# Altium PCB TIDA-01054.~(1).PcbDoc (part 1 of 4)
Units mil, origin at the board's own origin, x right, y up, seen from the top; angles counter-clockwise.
Board outline 4448 x 3930 mil, 4 copper layers (Layer 1 - Top Layer, Layer 2 - GND, Layer 3 - PWR, Layer 4 - Bottom Layer), stack 59.034 mil thick; 530 components, 282 nets, 1521 pads, 764 vias.
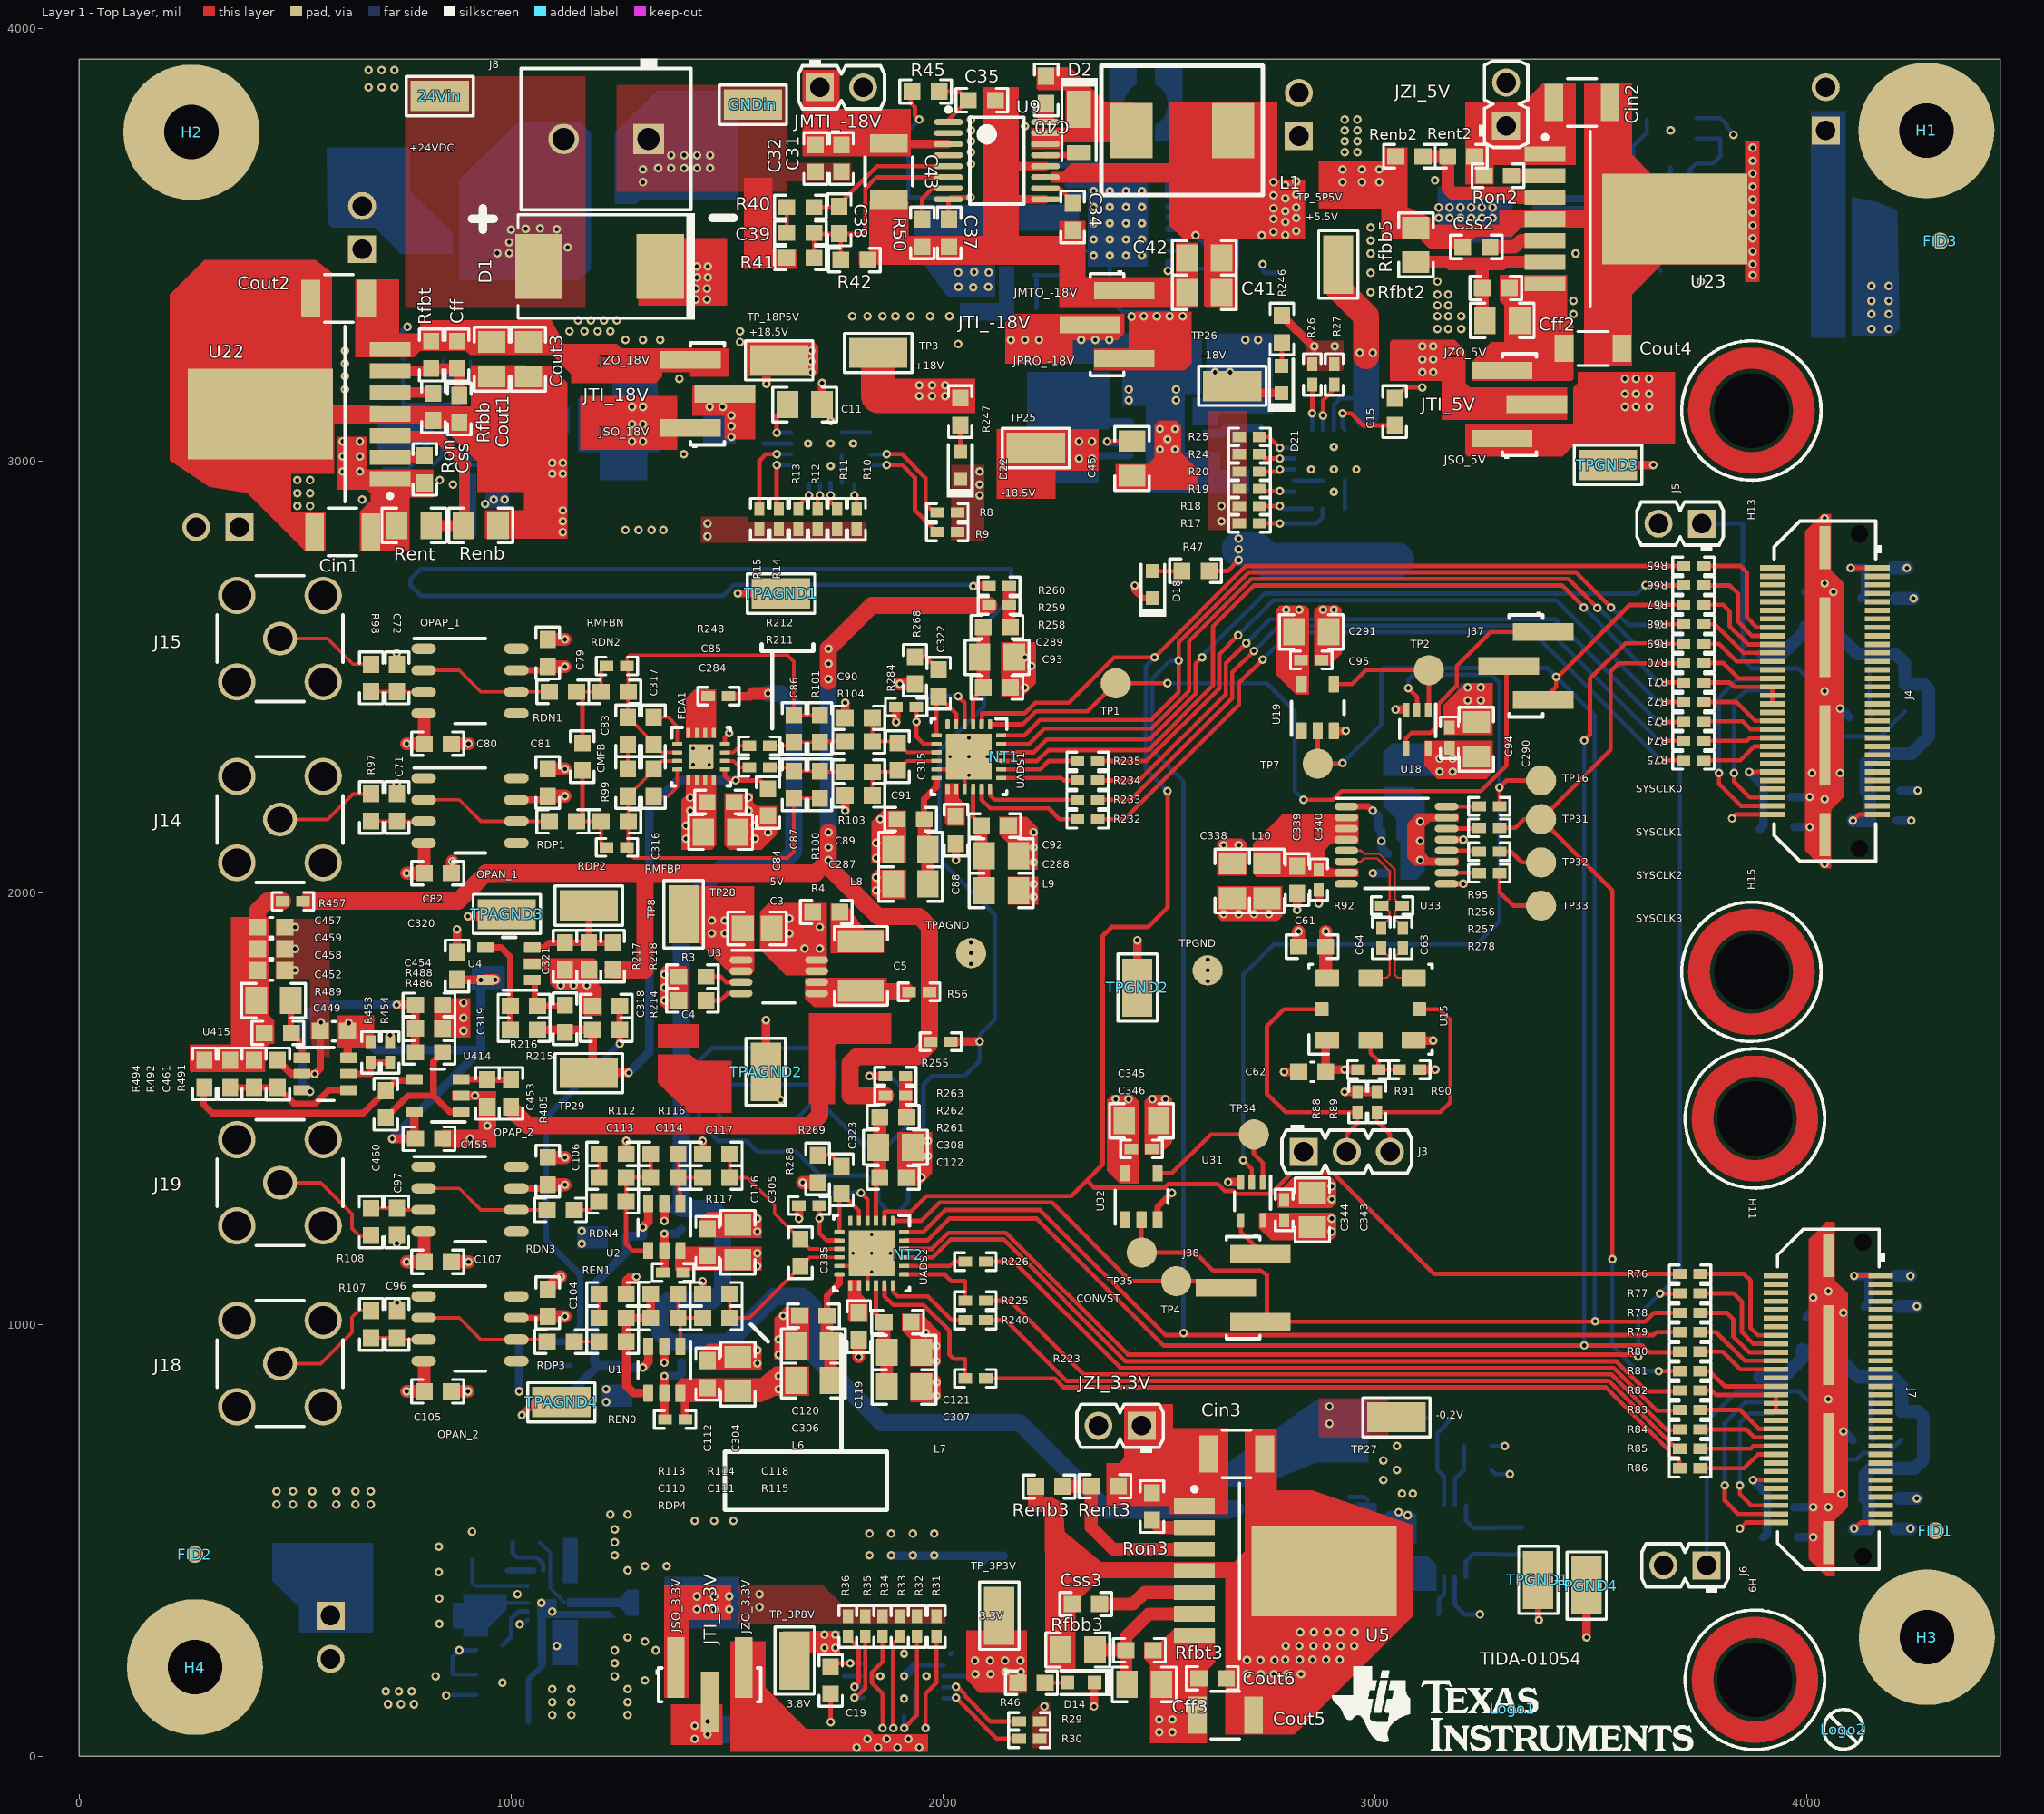
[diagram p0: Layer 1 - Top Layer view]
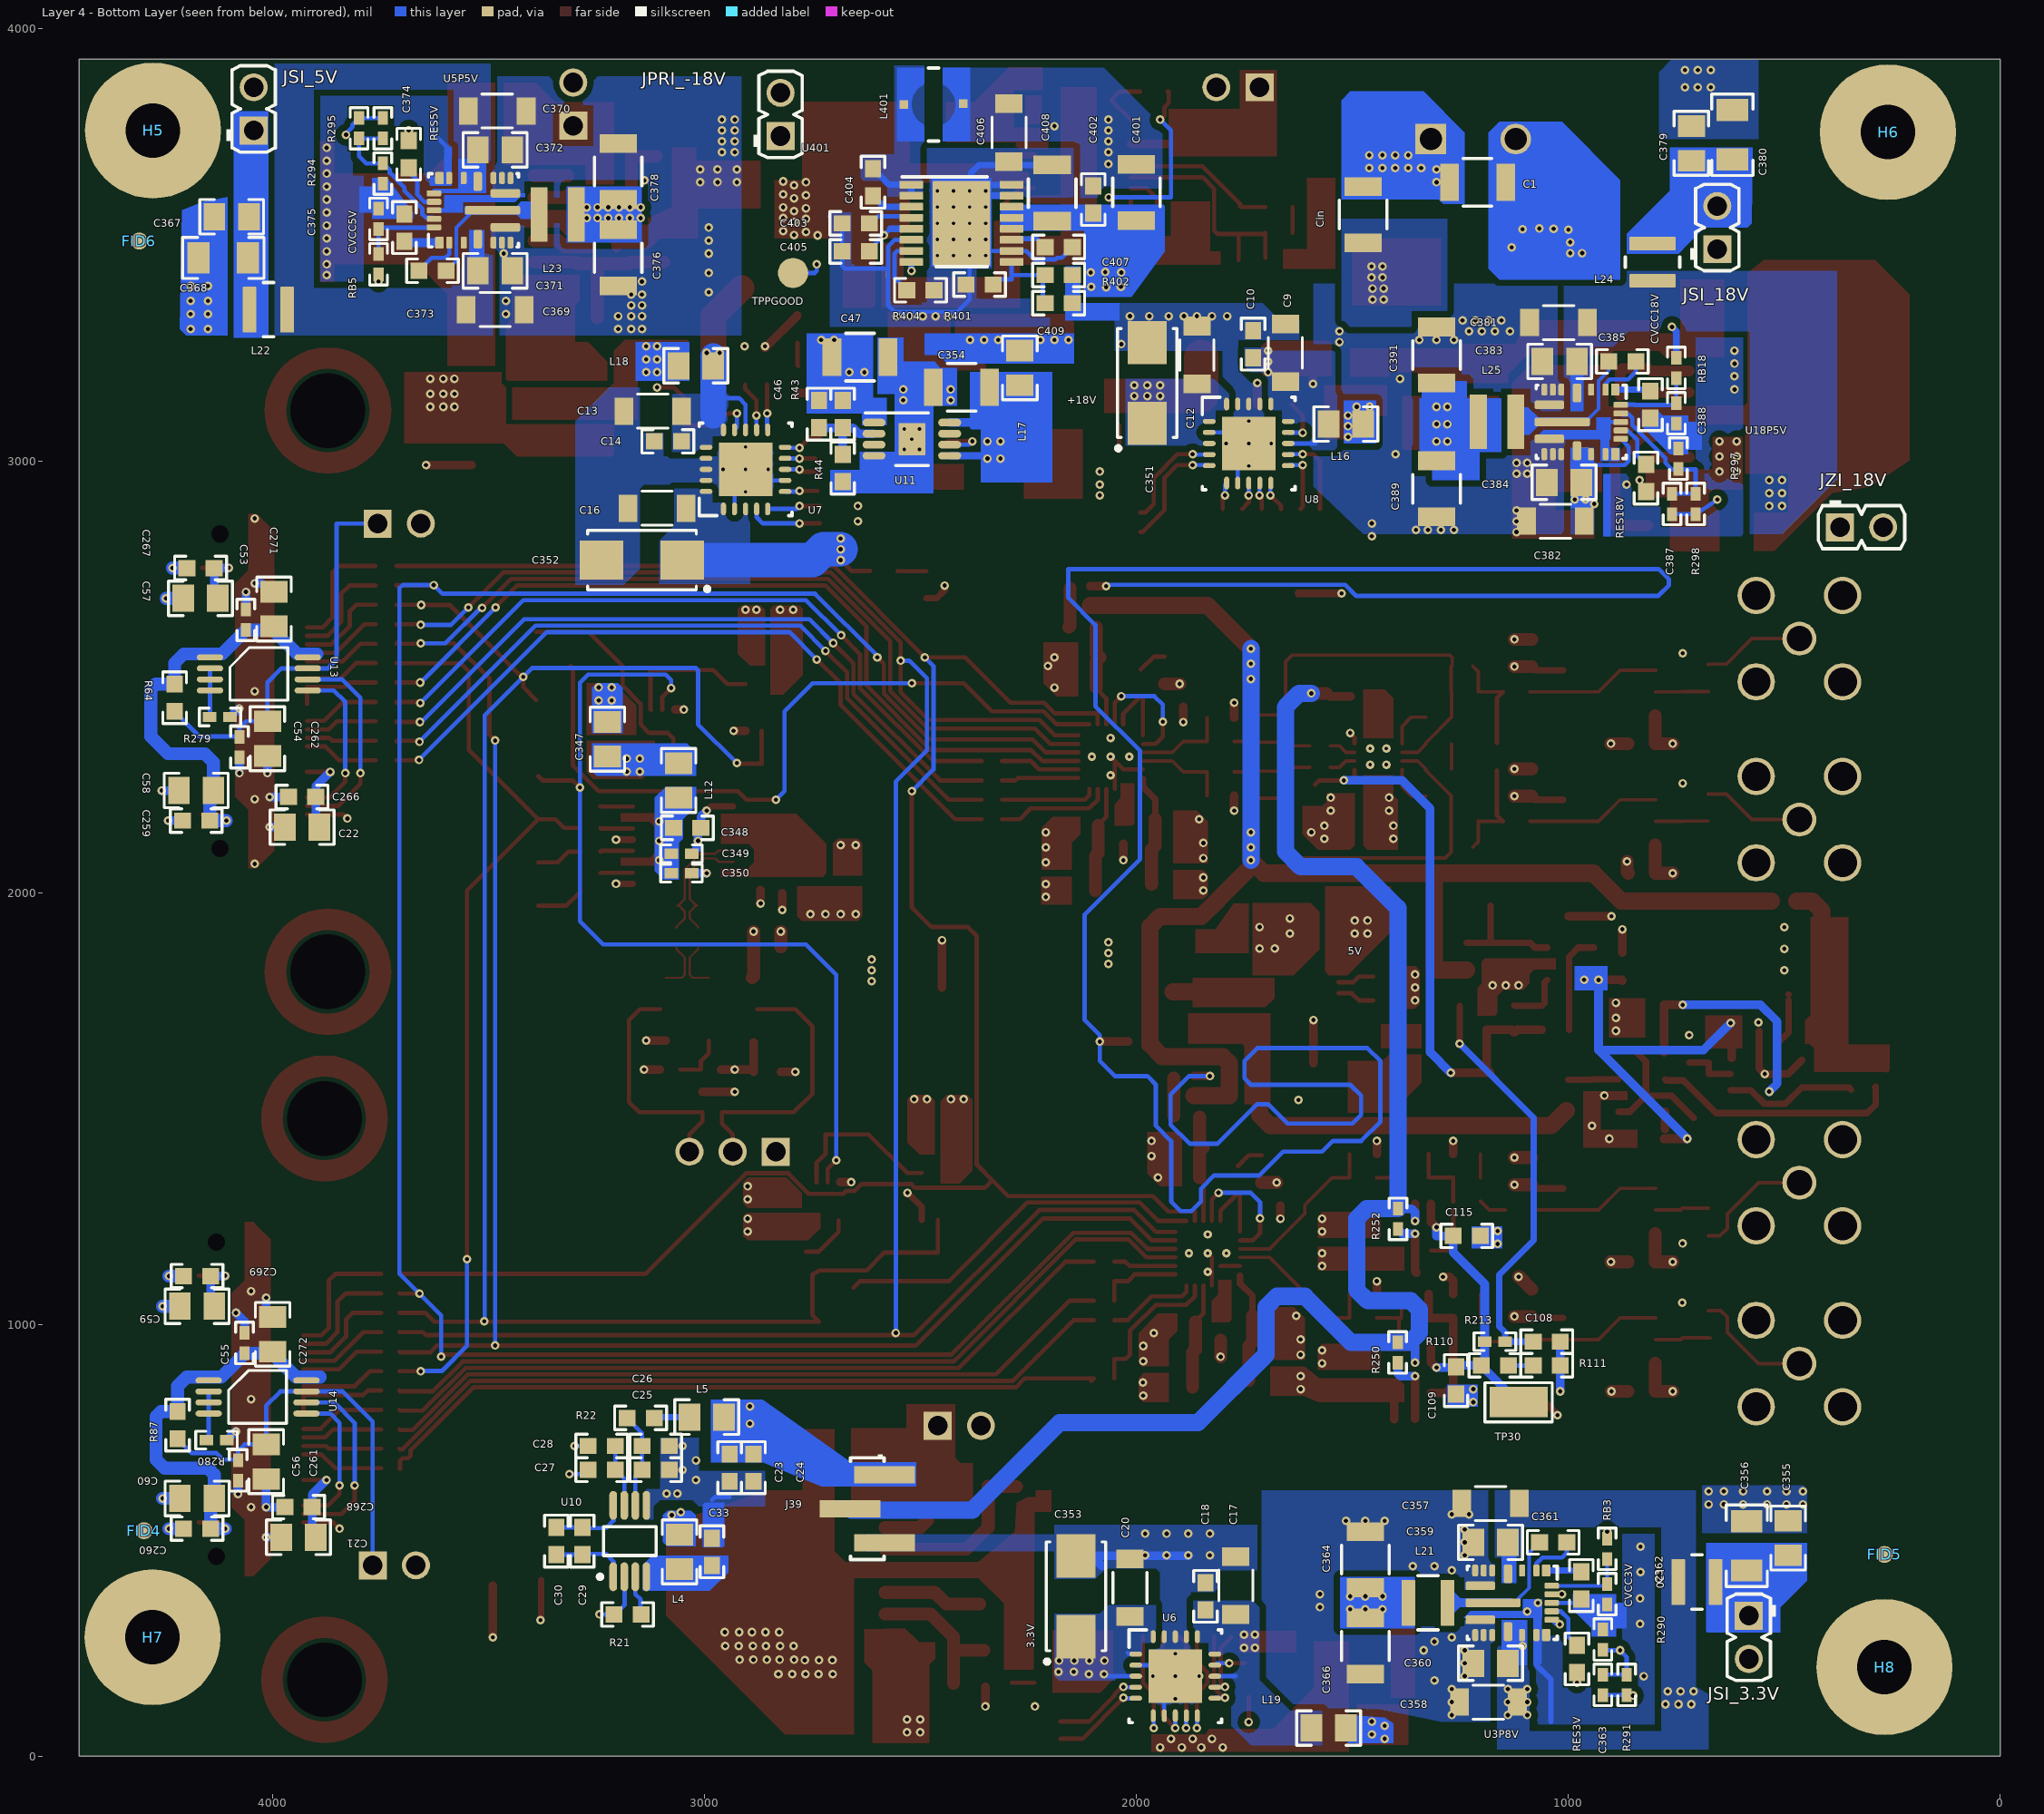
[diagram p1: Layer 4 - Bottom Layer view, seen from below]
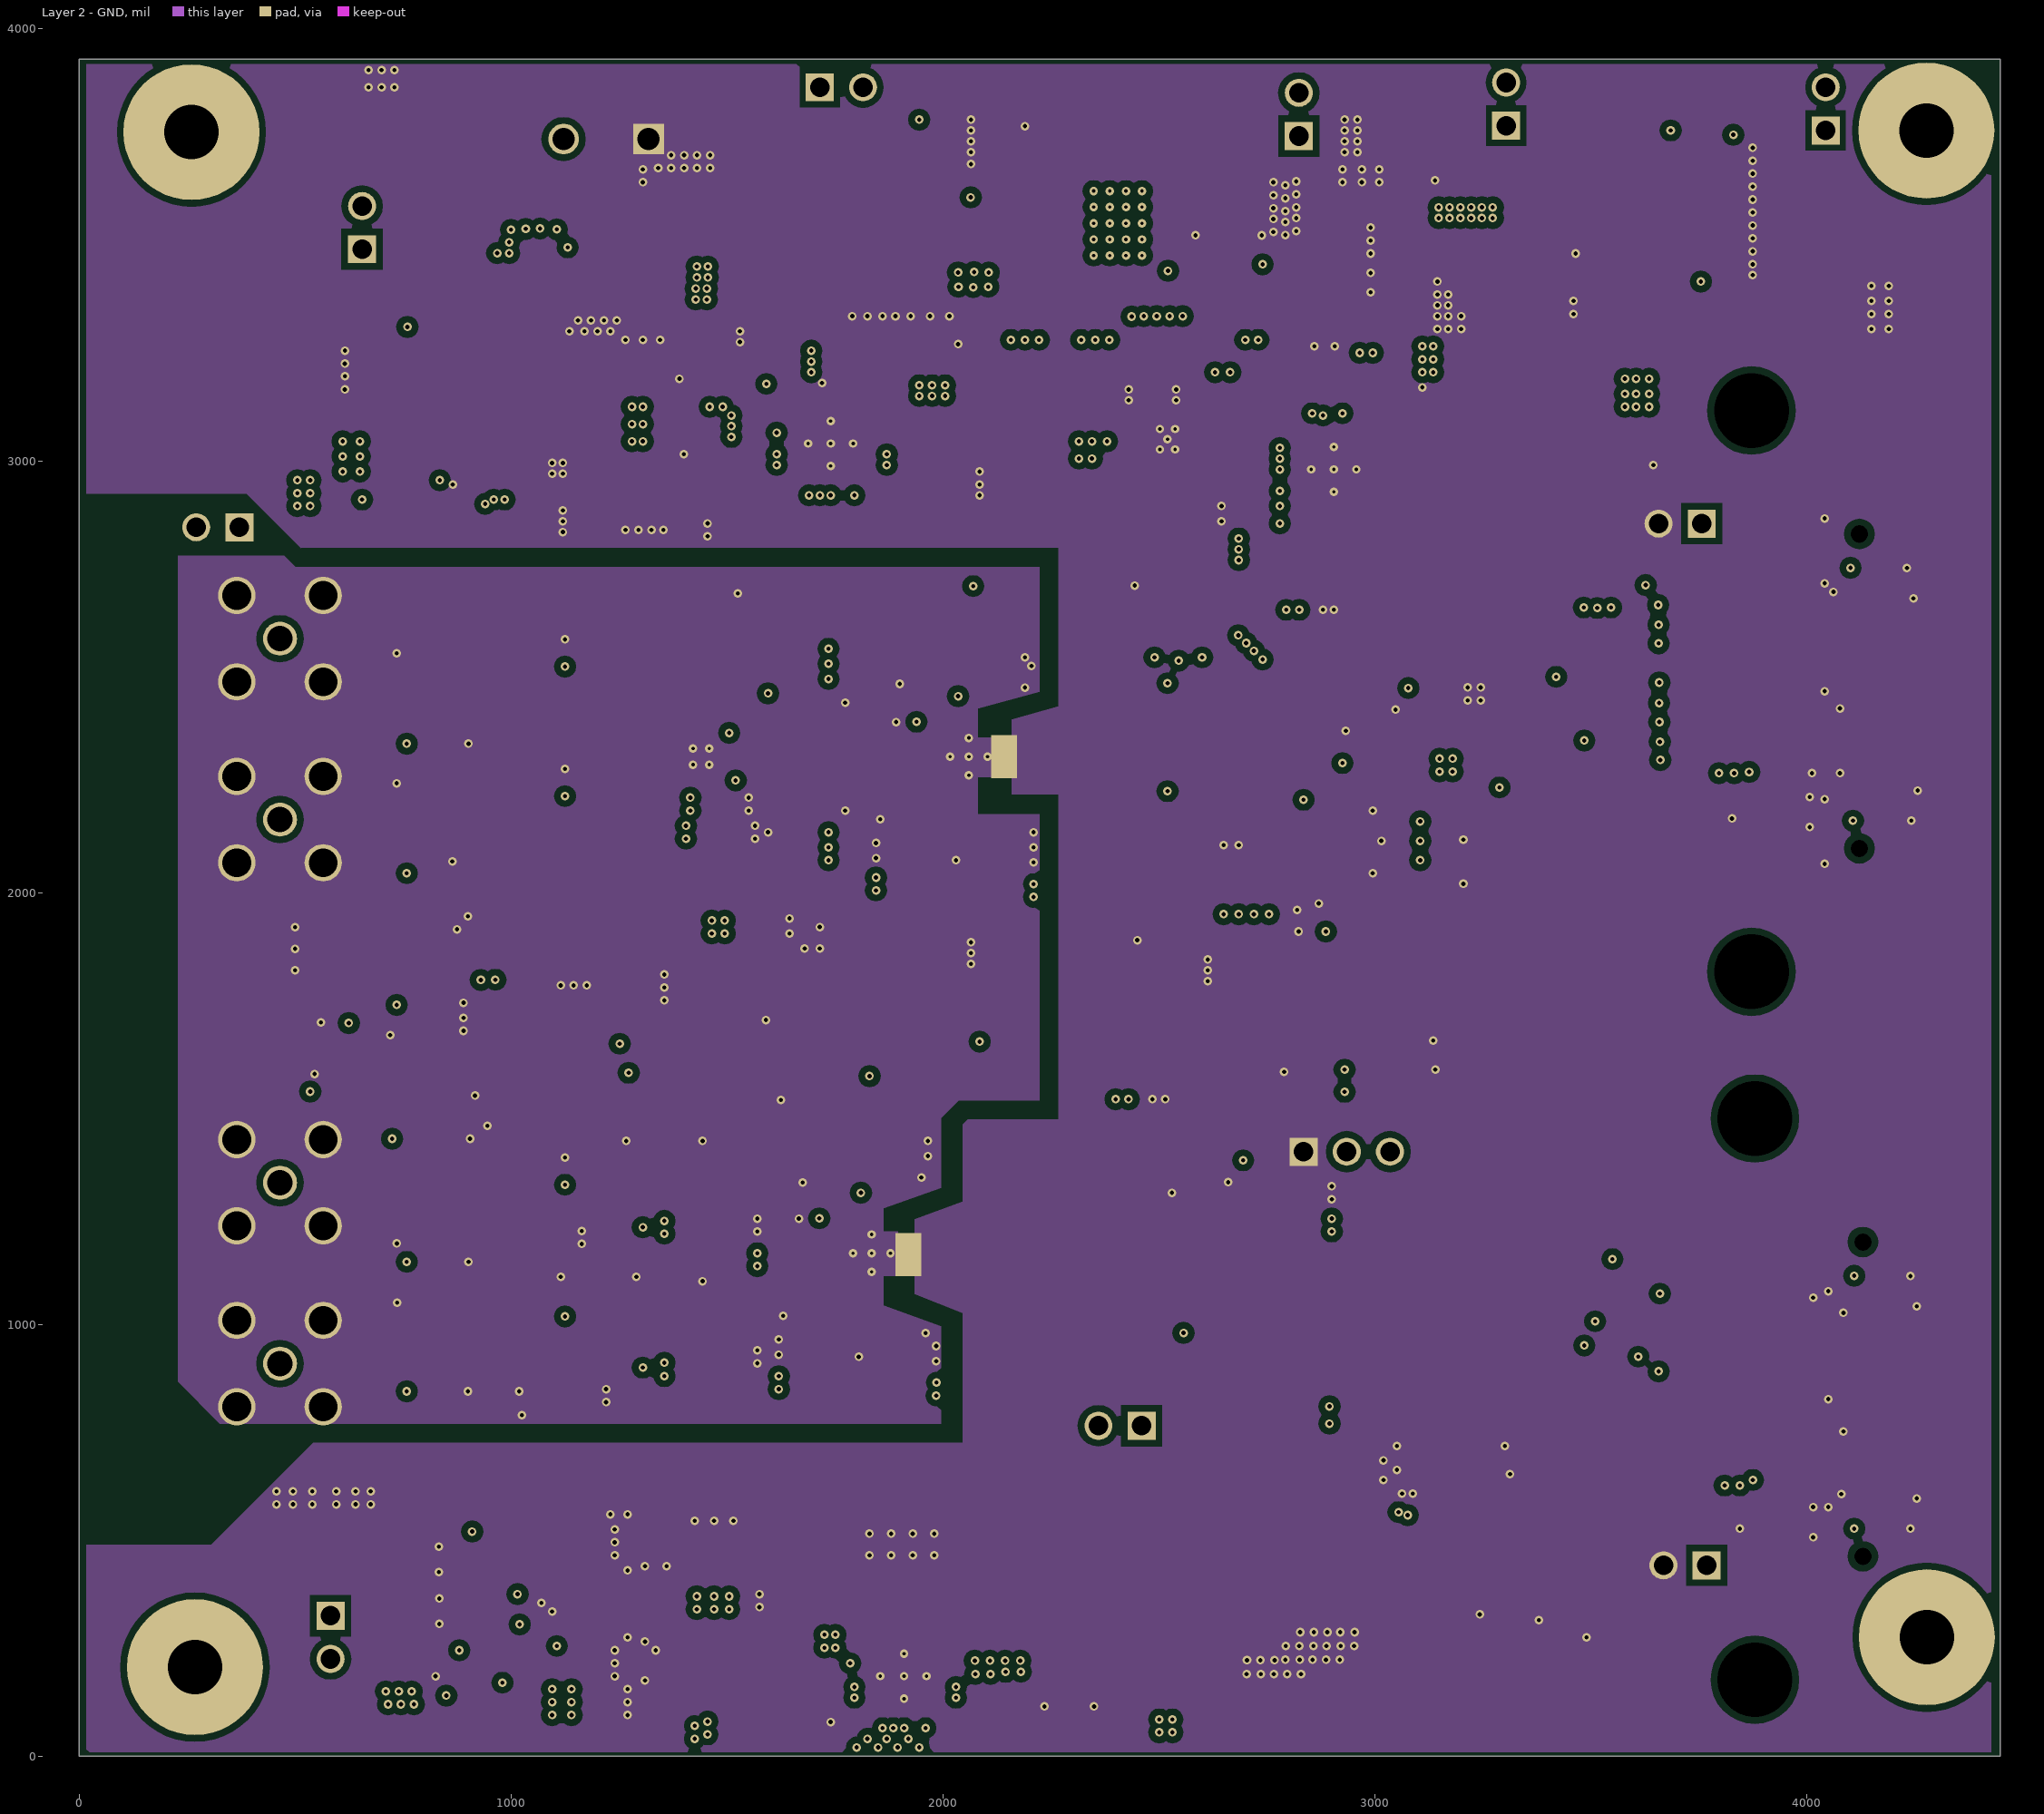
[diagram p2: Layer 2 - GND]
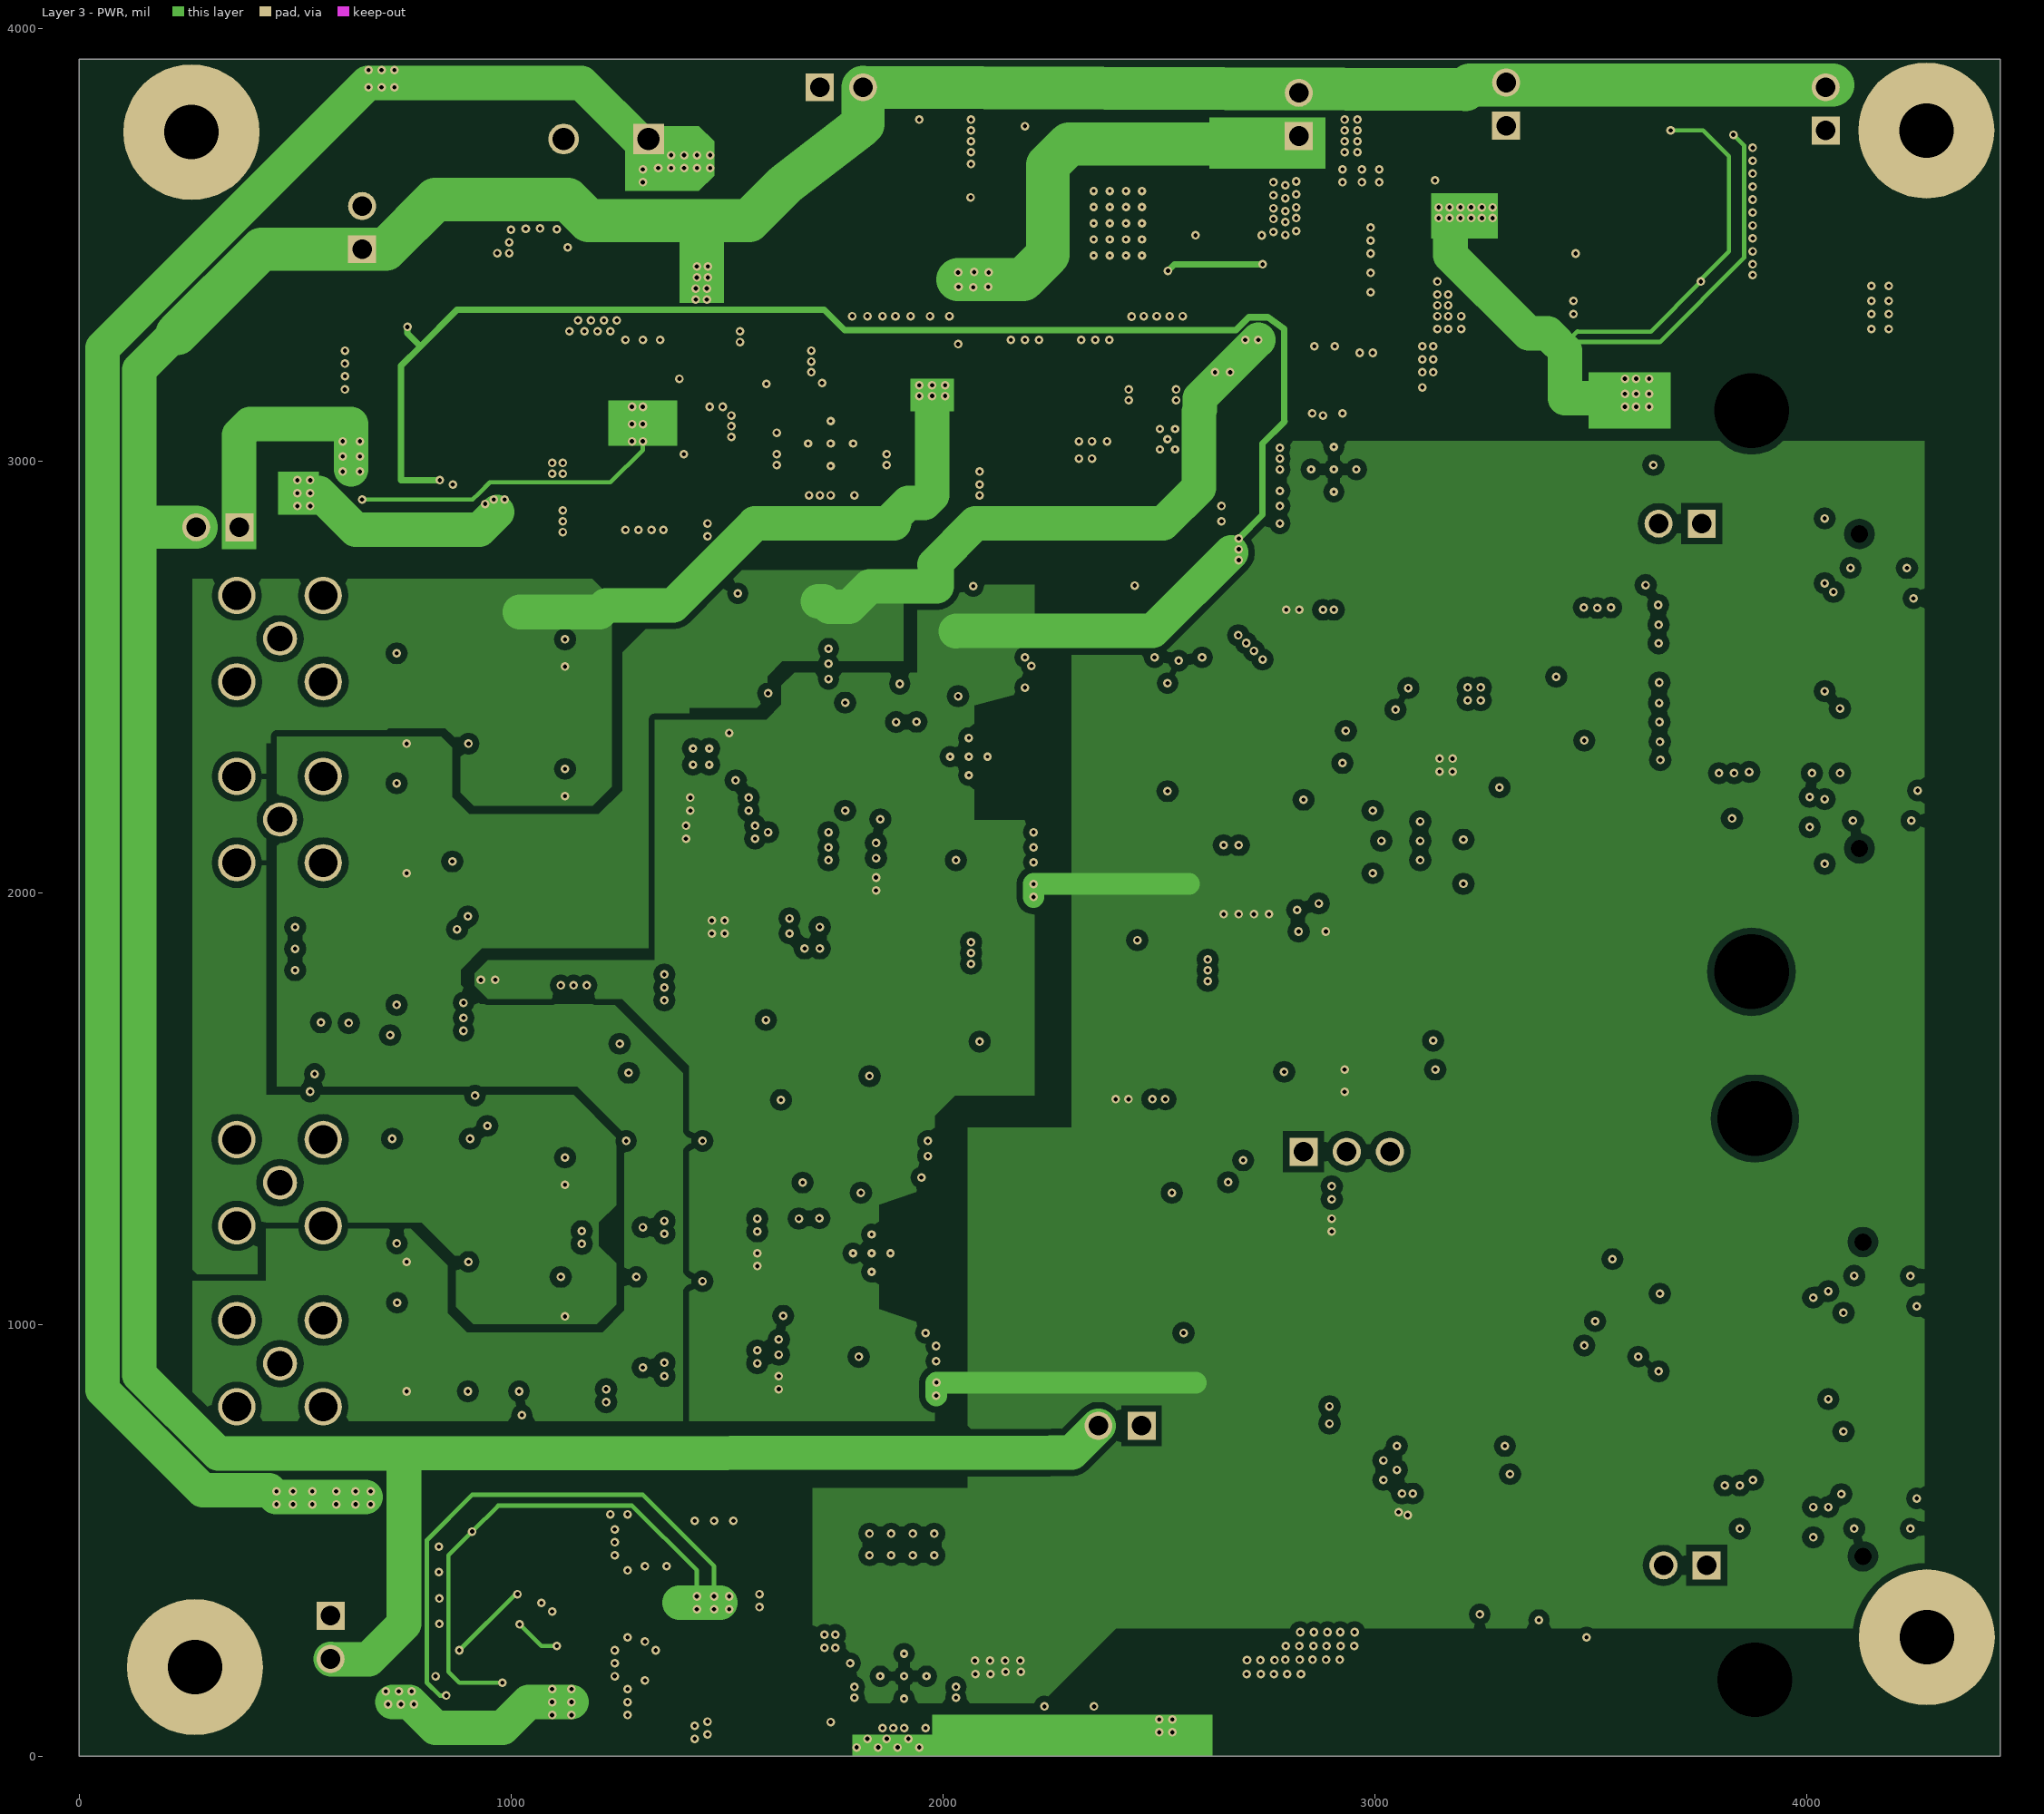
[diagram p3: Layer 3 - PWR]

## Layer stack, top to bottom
Top Solder: solder mask 0.4, Solder Resist, Dk 3.5
Layer 1 - Top Layer: signal copper 1.4
Dielectric 1: prepreg 5.2, 370HR, Dk 4.2
Layer 2 - GND: signal copper 1.417
Dielectric 2: core 43, 370HR, Dk 4.2
Layer 3 - PWR: signal copper 1.417
Dielectric 3: prepreg 5.2, 370HR, Dk 4.2
Layer 4 - Bottom Layer: signal copper 1.4
Bottom Solder: solder mask 0.4, Solder Resist, Dk 3.5

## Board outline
0,0 0,3930 4448,3930 4448,0

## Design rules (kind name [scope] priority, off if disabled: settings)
AcuteAngle [All] p1: minimum=4.50000000000000E+0001 checktracksonly=FALSE
AssemblyTestPointUsage [All] p1: valid=2
Clearance Clearance_Keepouts [((IsTrack Or IsArc) And Not InPoly) And IsFree and IsKeepOut vs ((IsTrack Or IsArc) And Not InPoly) And IsFree and IsKeepOut] p1: gap=0
Clearance Clearance_BoardEdge_MountingHoles [OnCopper and InComponentClass('Mounting Holes') vs IsKeepOut] p2: gap=40
Clearance Clearance_BoardEdge_Poly [OnCopper and InPoly vs IsKeepOut] p3: gap=25
Clearance Clearance_BoardEdge [OnCopper and Not InComponentClass('Logo') and not InComponentClass('FiducialMark') and not InRegion(1000,500,4000,800) and Not IsKeepout vs IsKeepOut] p4: gap=75
Clearance Clearance_Poly [InPolygon] p5: gap=15
Clearance [All] p6: gap=5
ComponentClearance ComponentClearance_MountingHoles_FiducialMarks [InComponentClass('Mounting Holes') vs InComponentClass('FiducialMark')] p1: gap=25 collisioncheckmode=3 verticalgap=10 showdistances=FALSE
ComponentClearance ComponentClearance_Shunt [InComponentClass('Header') vs InComponentClass('Shunt')] p2: gap=0 collisioncheckmode=3 verticalgap=0 showdistances=FALSE
ComponentClearance ComponentClearance_Logo [InComponentClass('Logo')] p3: gap=10 collisioncheckmode=3 verticalgap=10 showdistances=FALSE
ComponentClearance ComponentClearance_ScrewToNut [(HasFootprint('NY PMS 440 0025 PH')) vs (HasFootprint('Keystone_1902C'))] p4: gap=5 collisioncheckmode=3 verticalgap=10 showdistances=FALSE
ComponentClearance ComponentClearance_MountingHoles [InComponentClass('Mounting Holes')] p5: gap=15 collisioncheckmode=3 verticalgap=100000 showdistances=FALSE
ComponentClearance ComponentClearance_SmallPassives [HasFootprint('0201*') or HasFootprint('0402*') or HasFootprint('0508') or HasFootprint('0603*') or HasFootprint('0612') or HasFootprint('0805*') or HasFootprint('0815*') or HasFootprint('0830*') or HasFootprint('1206*') or HasFootprint('1210*') or HasFootprint('1808*') or HasFootprint('1812*') or HasFootprint('1825*') or HasFootprint('2010*') or HasFootprint('2220*') or HasFootprint('2225*') or HasFootprint('2512*') or HasFootprint('2728*') or HasFootprint('3518*') vs HasFootprint('0201*') or HasFootprint('0402*') or HasFootprint('0508') or HasFootprint('0603*') or HasFootprint('0612') or HasFootprint('0805*') or HasFootprint('0815*') or HasFootprint('0830*') or HasFootprint('1206*') or HasFootprint('1210*') or HasFootprint('1808*') or HasFootprint('1812*') or HasFootprint('1825*') or HasFootprint('2010*') or HasFootprint('2220*') or HasFootprint('2225*') or HasFootprint('2512*') or HasFootprint('2728*') or HasFootprint('3518*')] p6: gap=5 collisioncheckmode=3 verticalgap=10 showdistances=FALSE
ComponentClearance ComponentClearance_THtoSMT [IsThruComponent vs IsSMTComponent] p7: gap=10 collisioncheckmode=3 verticalgap=30 showdistances=FALSE
ComponentClearance ComponentClearance_THtoTH [IsThruComponent vs IsThruComponent] p8: gap=75 collisioncheckmode=3 verticalgap=30 showdistances=FALSE
ComponentClearance [All] p9: gap=5 collisioncheckmode=3 verticalgap=10 showdistances=FALSE
DiffPairsRouting [All] p1: maxlimit=20 minlimit=6 mostfreqgap=6 toplayer_minwidth=5 toplayer_maxwidth=5 toplayer_prefwidth=5 midlayer1_minwidth=5 midlayer1_maxwidth=5 midlayer1_prefwidth=5 midlayer2_minwidth=5 midlayer2_maxwidth=5 midlayer2_prefwidth=5 bottomlayer_minwidth=5 bottomlayer_maxwidth=5 bottomlayer_prefwidth=5 maxuncoupledlength=1000
FabricationTestPointUsage TestPointUsage [All] p1: valid=2 allowmultiple=FALSE
FabricationTestpoint Testpoint [All] p1: side=3 testpointundercomponent=TRUE minsize=40 maxsize=100 preferedsize=60 minholesize=0 maxholesize=40 preferedholesize=32 testpointgrid=1 allowsidetop=TRUE allowsidebottom=TRUE usegrid=TRUE gridtolerance=0.01
FanoutControl Fanout_LCC [IsLCC] p1: bgadir=Out bgaviamode=Centered fanoutstyle=Auto fanoutdirection=Alternating viagrid=1 // Fanout_LCC (Default Rule)
FanoutControl Fanout_BGA [IsBGA] p2: bgadir=Out bgaviamode=Centered fanoutstyle=Auto fanoutdirection=Alternating viagrid=1 // Fanout_BGA (Default Rule)
FanoutControl Fanout_Default [All] p4: bgadir=Out bgaviamode=Centered fanoutstyle=Auto fanoutdirection=Alternating viagrid=1 // Fanout_Default (Default Rule)
FanoutControl Fanout_Small [(CompPinCount < 5)] p5: bgadir=Out bgaviamode=Centered fanoutstyle=Auto fanoutdirection=OutThenIn viagrid=1 // Fanout_Small (Default Rule)
HoleSize [All] p1: absolutevalues=TRUE maxlimit=251 minlimit=6 maxpercent=80.000 minpercent=20.000
MinimumAnnularRing MinimumAnnularRing_ThermalPadVias [IsVia and InAnyComponent] p1: minimumring=5.91
MinimumAnnularRing [All] p2: minimumring=5
MinimumSolderMaskSliver MinimumSolderMaskSliver_Logo [InComponentClass('Logo') vs InComponentClass('Logo')] p1: minsoldermaskwidth=0
MinimumSolderMaskSliver [All] p2: minsoldermaskwidth=0
PlaneConnect [All] p1: planeconnectstyle=Direct reliefexpansion=10 reliefentries=4 reliefconductorwidth=10 reliefairgap=10
PolygonConnect PolygonConnect_1 [All vs IsNamedPolygon('AGND_L02_P018')] p1: connectstyle=Direct reliefconductorwidth=10 reliefentries=4 polygonreliefangle="90 Angle" airgapwidth=10
PolygonConnect [All] p2: connectstyle=Direct reliefconductorwidth=10 reliefentries=4 polygonreliefangle="90 Angle" airgapwidth=10
RoutingVias ThermalPadVias [IsVia and InAnyComponent] p1: holewidth=7.87 width=19.68 viastyle="Through Hole" minholewidth=7.87 minwidth=19.68 maxholewidth=12.99 maxwidth=23.62
RoutingVias [All] p2: holewidth=16 width=34 viastyle="Through Hole" minholewidth=7.87 minwidth=20 maxholewidth=40 maxwidth=65
SilkToBoardRegionClearance [Not ((IsComment or IsDesignator) And (Hide <> 'False')) and not InRegion(1000,500,4000,800)] p1:
SilkToSilkClearance SilkToSilkClearance_Pb-FreeLogo [(HasFootprint('Pb-Free_Overlay_Medium') OR HasFootprint('Pb-Free_Overlay_Small')) vs (HasFootprint('Pb-Free_Overlay_Medium') OR HasFootprint('Pb-Free_Overlay_Small'))] p1: silktosilkclearance=0
SilkToSilkClearance [All] p2: silktosilkclearance=0
SilkToSolderMaskClearance SilkToComonentPadClearance [IsPad and InAnycomponent] p1: minsilkscreentomaskgap=0 clearancetoexposedcopper=TRUE
SilkToSolderMaskClearance "Silk to Solder Mask Opening" [All] p2: minsilkscreentomaskgap=0 clearancetoexposedcopper=FALSE
SolderMaskExpansion [All] p1: expansion=1.97
Width Width_DA1_N [InNet('DA1_N')] p1: maxlimit=10 minlimit=5 preferedwidth=5 impedancedriven=TRUE minimp=50.000000 maximp=50.000000 favimp=50.000000
Width Width_DA2_N [InNet('DA2_N')] p2: maxlimit=10 minlimit=5 preferedwidth=5 impedancedriven=TRUE minimp=50.000000 maximp=50.000000 favimp=50.000000
Width Width_DA1_P [InNet('DA1_P')] p3: maxlimit=10 minlimit=5 preferedwidth=5 impedancedriven=TRUE minimp=50.000000 maximp=50.000000 favimp=50.000000
Width Width_DA2_P [InNet('DA2_P')] p4: maxlimit=10 minlimit=5 preferedwidth=5 impedancedriven=TRUE minimp=50.000000 maximp=50.000000 favimp=50.000000
Width Width_VIN+1_P [InNet('VIN+_1_P')] p5: maxlimit=10 minlimit=5 preferedwidth=5 impedancedriven=TRUE minimp=50.000000 maximp=50.000000 favimp=50.000000
Width Width_VIN+2_N [InNet('VIN+_2_N')] p6: maxlimit=10 minlimit=5 preferedwidth=5 impedancedriven=TRUE minimp=50.000000 maximp=50.000000 favimp=50.000000
Width Width_VIN+2_P [InNet('VIN+_2_P')] p7: maxlimit=10 minlimit=5 preferedwidth=5 impedancedriven=TRUE minimp=50.000000 maximp=50.000000 favimp=50.000000
Width Width_VIN+1_N [InNet('VIN+_1_N')] p8: maxlimit=10 minlimit=5 preferedwidth=5 impedancedriven=TRUE minimp=50.000000 maximp=50.000000 favimp=50.000000
Width [All] p9: maxlimit=100 minlimit=5 preferedwidth=10 checkconnectedcopper=TRUE
15 further rules are at their usual default settings.

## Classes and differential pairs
component class "OPA625 ADC Driver_Power_1050": C31 C32 C34 C35 C37 C38 C39 C40 C41 C42 C43 Cff Cff2 Cff3 Cin1 Cin2 Cin3 Cout1 Cout2 Cout3 Cout4 Cout5 Cout6 Css Css2 Css3 D2 JMTI_-18V JZI_3.3V JZI_5V JZI_18V L1 R40 R41 R42 R45 R50 Renb Renb2 Renb3 Rent Rent2 Rent3 Rfbb Rfbb3 Rfbb5 Rfbt Rfbt2 Rfbt3 Ron Ron2 Ron3 U5 U9 U22 U23
component class AssemblyNote: ZZ2 ZZ3 ZZ4
component class FiducialMark: FID1 FID2 FID3 FID4 FID5 FID6
component class "OPA625 ADC Driver_Hardware": FID1 FID2 FID3 FID4 FID5 FID6 H1 H2 H3 H4 H5 H6 H7 H8 H9 H11 H13 H15 Logo1 Logo2 ZZ2 ZZ3 ZZ4
component class Logo: Logo1
component class "Mounting Holes": H1 H2 H3 H4
component class Header: J3 J5 J6 J37 J38 J39 JMTI_-18V JPRI_-18V JSI_3.3V JSI_5V JSI_18V JTI_3.3V JTI_5V JTI_18V JTI_-18V JZI_3.3V JZI_5V JZI_18V
component class "OPA625 ADC Driver_Clock": C61 C62 C63 C64 C338 C339 C340 C347 C348 C349 C350 J3 L10 L12 R88 R89 R90 R91 R92 R95 R256 R257 R278 TP16 TP31 TP32 TP33 U15 U33
component class "OPA625 ADC Driver_Connectors": C21 C22 C53 C54 C55 C56 C57 C58 C59 C60 C259 C260 C261 C262 C266 C267 C268 C269 C271 C272 J4 J5 J6 J7 R64 R65 R66 R67 R68 R69 R70 R71 R72 R73 R74 R75 R76 R77 R78 R79 R80 R81 R82 R83 R84 R85 R86 R87 R279 R280 U13 U14
component class "OPA625 ADC Driver_OPA625 ADC Driver REV1.0": C3 C4 C5 C71 C72 C79 C80 C81 C82 C83 C84 C85 C86 C87 C88 C89 C90 C91 C92 C93 C94 C95 C96 C97 C104 C105 C106 C107 C108 C109 C110 C111 C112 C113 C114 C115 C116 C117 C118 C119 C120 C121 C122 C284 C287 C288 C289 C290 C291 C304 C305 C306 C307 C308 C315 C316 C317 C318 C319 C320 C321 C322 C323 C335 C343 C344 C345 C346 C449 C452 C453 C454 C455 C457 C458 C459 C460 C461 CMFB FDA1 J14 J15 J18 J19 J37 J38 L6 L7 L8 L9 OPAN_1 OPAN_2 OPAP_1 OPAP_2 R3 R4 R56 R97 R98 R99 R100 R101 R103 R104 R107 R108 R110 R111 R112 R113 R114 R115 R116 R117 R211 R212 R213 R214 R215 R216 R217 R218 R223 R225 R226 R232 R233 R234 R235 R240 R248 R250 R252 R255 R258 R259 R260 R261 R262 R263 R268 R269 R284 R288 R453 R454 R457 R485 R486 R488 R489 R491 R492 R494 RDN1 RDN2 RDN3 RDN4 RDP1 RDP2 RDP3 RDP4 REN0 REN1 RMFBN RMFBP TP1 Tp2 TP4 TP7 TP28 TP29 TP30 TP34 TP35 TPAGND U1 U2 U3 U4 U18 U19 U31 U32 U414 U415 UADS1 UADS2
component class "OPA625 ADC Driver_Power_1054": 24Vin C1 C9 C10 C11 C12 C13 C14 C15 C16 C17 C18 C19 C20 C23 C24 C25 C26 C27 C28 C29 C30 C33 C45 C46 C47 C351 C352 C353 C354 C355 C356 C357 C358 C359 C360 C361 C362 C363 C364 C366 C367 C368 C369 C370 C371 C372 C373 C374 C375 C376 C378 C379 C380 C381 C382 C383 C384 C385 C387 C388 C389 C391 C401 C402 C403 C404 C405 C406 C407 C408 C409 Cin CVCC3V CVCC5V CVCC18V D1 D14 D18 D21 D22 GNDin J8 J39 JPRI_-18V JSI_3.3V JSI_5V JSI_18V JTI_3.3V JTI_5V JTI_18V JTI_-18V L4 L5 L16 L17 L18 L19 L20 L21 L22 L23 L24 L25 L401 NT1 NT2 R8 R9 R10 R11 R12 R13 R14 R15 R17 R18 R19 R20 R21 R22 R24 R25 R26 R27 R29 R30 R31 R32 R33 R34 R35 R36 R43 R44 R46 R47 R246 R247 R290 R291 R294 R295 R297 R298 R401 R402 R404 RB3 RB5 RB18 RES3V RES5V RES18V TP3 TP8 TP25 TP26 Tp27 TP_3P3V TP_3P8V TP_5P5V TP_18P5V TPAGND1 TPAGND2 TPAGND3 TPAGND4 TPGND TPGND1 TPGND2 TPGND3 TPGND4 TPPGOOD U3P8V U5P5V U6 U7 U8 U10 U11 U18P5V U401
differential pair BCLK0: +BCLK0_P -BCLK0_N
differential pair BCLK1: +BCLK1_P -BCLK1_N

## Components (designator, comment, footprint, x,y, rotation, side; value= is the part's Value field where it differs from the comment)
24Vin "5015" Testpoint_Keystone_Miniature 835,3845 r0 top
C1 "UMK325AB7106KM-T" 1210_280 1210,3645 r0 bottom
C3 "GRM21BR71A106KE51L" 0805 1569.79,1916.65 r180 top
C4 "GRM188R71A105KA61D" 0603#1 1420,1750.16 r180 top
C5 "GRM32ER71A476KE15L" 1210_270 1810,1830.16 r90 top
C9 "C3216X5R1E476M160AC" 1206_190 1655,3250 r90 bottom
C10 "CGA3E2X7R2A102K080AA" 0603#1 1730,3270 r90 bottom
C11 "C2012X7S2A105K125AB" 0805_HV 1680,3130 r0 top
C12 "C3216X5R1E476M160AC" 1206_190 1860,3245 r90 bottom
C13 "C3216X5R1E476M160AC" 1206_190 3120,3115 r0 bottom
C14 "GRM1885C1H102FA01J" 0603#1 3085,3045 r0 bottom
C15 "GRM188R71E105KA12D" 0603#1 3046.02,3113.66 r270 top
C16 "C3216X5R1E476M160AC" 1206_190 3110,2890 r0 bottom
C17 "C3216X5R1E476M160AC" 1206_190 1770,395 r90 bottom
C18 "GRM1885C1H102FA01J" 0603#1 1840,370 r90 bottom
C19 "GRM188R71E105KA12D" 0603#1 1740,175 r90 top
C20 "C3216X5R1E476M160AC" 1206_190 2015,390 r90 bottom
C21 "GRM21BR71A106KE51L" 0805_HV 3940.02,506.69 r0 bottom
C22 "GRM21BR71A106KE51L" 0805_HV 3932.01,2151.39 r0 bottom
C23 "GRM188R61A106ME69D" 0603#1 2941.79,668 r270 bottom
C24 "GRM188R61A106ME69D" 0603#1 2886.79,668 r270 bottom
C25 "GRM188R71E474KA12D" 0603#1 3113.02,663 r180 bottom
C26 "GRM188R60J226MEA0D" 0603#1 3113.02,718 r180 bottom
C27 "GRM188R61C104KA01D" 0603#1 3238.02,663 r0 bottom
C28 "GRM188R60J226MEA0D" 0603#1 3238.02,718 r0 bottom
C29 "GRM188R61A475MAAJ" 0603#1 3283.02,498 r90 bottom
C30 "GRM188R61A224KA01D" 0603#1 3343.02,498 r90 bottom
C31 "GCM188R71H224KA64D" 0603#1 1765,3700 r270 top
C32 "C1608X7R1H104K080AA" 0603#1 1705,3700 r270 top
C33 "GRM188R61A106ME69D" 0603#1 2983.02,473 r90 bottom
C34 "GRM188R71H333KA61D" 0603#1 2300,3565 r270 top
C35 "C1608X7R1H104K080AA" 0603#1 2090,3835 r0 top
C37 "C0603C911J5GACTU" 0603#1 2014.22,3527.56 r270 top
C38 "CGA3E2C0G1H100D080AA" 0603#1 1760.02,3557.8 r90 top
C39 "GRM1885C1H151JA01D" 0603#1 1670.02,3527.8 r180 top
C40 "GRM188R71H223KA01D" 0603#1 2239,3859 r270 top
C41 "C2012X5R1V226M125AC" 0805_HV 2605,3390 r180 top
C42 "C2012X7S2A105K125AB" 0805_HV 2605,3470 r180 top
C43 "UMK325AB7106KM-T" 1210_280 1875,3670 r270 top
C45 "C2012X7S2A105K125AB" 0805_HV 2437.74,3005.49 r270 top
C46 "GCM188R71H103KA37D" 0603#1 2735,3108.05 r270 bottom
C47 "UMK325AB7106KM-T" 1210_280 2640,3240 r180 bottom
C53 "GRM155R71C104KA88D" 0402 4062,2631.4 r270 bottom
C54 "GRM155R71C104KA88D" 0402 4077.01,2336.39 r90 bottom
C55 "GRM155R71C104KA88D" 0402 4065.02,956.69 r270 bottom
C56 "GRM155R71C104KA88D" 0402 4080.03,661.69 r90 bottom
C57 "GRM21BR71A106KE51L" 0805_HV 4167.01,2681.39 r0 bottom
C58 "GRM21BR71A106KE51L" 0805_HV 4177.01,2236.39 r0 bottom
C59 "GRM21BR71A106KE51L" 0805_HV 4175.03,1041.69 r0 bottom
C60 "GRM21BR71A106KE51L" 0805_HV 4175.03,596.69 r0 bottom
C61 "C0603C104J3RACTU" 0603#1 2855,1874.74 r180 top
C62 "ZRB18AD71A106KE01L" 0603_120#1 2855,1584.75 r180 top
C63 "GRM155R61E104KA87D" 0402 3065,1894.75 r90 top
C64 "GRM155R61E104KA87D" 0402 3015,1894.75 r90 top
C71 "GRM1885C2A100JA01D" 0603#1 736,2197 r270 top
C72 "GRM1885C2A100JA01D" 0603#1 736,2497 r270 top
C79 "GRM188R72A104KA35D" 0603#1 1085,2554.75 r270 top
C80 "GRM188R72A104KA35D" 0603#1 830,2344.75 r180 top
C81 "GRM188R72A104KA35D" 0603#1 1085,2254.75 r270 top
C82 "GRM188R72A104KA35D" 0603#1 829.99,2044.74 r180 top
C83 "GRM1885C2A680JA01D" 0603#1 1270,2374.75 r90 top
C84 "C0603C104J3RACTU" 0603#1 1595,2208.75 r270 top
C85 "C0603C104J3RACTU" 0603#1 1485,2209.75 r0 top
C86 "GRM1885C2A270JA01D" 0603#1 1655,2379.75 r90 top
C87 "GRM1885C2A270JA01D" 0603#1 1655,2249.75 r270 top
C88 "GRM188R71A105KA61D" 0603#1 2030,2144.75 r90 top
C89 "C1608C0G2A102J080AA" 0603#1 1805,2224.75 r180 top
C90 "C1608C0G2A102J080AA" 0603#1 1805,2404.75 r180 top
C91 "C0603C104J3RACTU" 0603#1 1925,2169.75 r0 top
C92 "C0603C104J3RACTU" 0603#1 2120,2154.75 r0 top
C93 "C0603C104J3RACTU" 0603#1 2125,2474.75 r0 top
C94 "GRM155R71C104KA88D" 0402 3172.81,2358.54 r270 top
C95 "GRM155R71C104KA88D" 0402 2852.81,2538.54 r180 top
C96 "GRM1885C2A100JA01D" 0603#1 736,1000 r270 top
C97 "GRM1885C2A100JA01D" 0603#1 735.7,1237.35 r90 top
C104 "GRM188R72A104KA35D" 0603#1 1085,1049.75 r270 top
C105 "GRM188R72A104KA35D" 0603#1 830,844.75 r180 top
C106 "GRM188R72A104KA35D" 0603#1 1085,1354.75 r270 top
C107 "GRM188R72A104KA35D" 0603#1 830,1144.75 r180 top
C108 "C0603C104J3RACTU" 0603#1 1050,959.75 r180 bottom
C109 "C0603C102J5GAC" 0603#1 1260,869.75 r270 bottom
C110 "C1608C0G2A471J" 0603#1 1235,1014.75 r0 top
C111 "C1608C0G2A101F080AA" 0603#1 1355,1014.75 r180 top
C112 "C0603C104J3RACTU" 0603#1 1455,884.75 r270 top
C113 "C1608C0G2A471J" 0603#1 1235,1339.75 r180 top
C114 "C1608C0G2A101F080AA" 0603#1 1355,1339.75 r180 top
C115 "C0603C102J5GAC" 0603#1 1235,1204.75 r180 bottom
C116 "C0603C104J3RACTU" 0603#1 1455,1189.75 r270 top
C117 "C1608C0G2A102J080AA" 0603#1 1475,1394.75 r180 top
C118 "C1608C0G2A102J080AA" 0603#1 1475,1069.75 r180 top
C119 "GRM188R71A105KA61D" 0603#1 1805,994.75 r270 top
C120 "C0603C104J3RACTU" 0603#1 1700,1019.75 r0 top
C121 "C0603C104J3RACTU" 0603#1 1895,1004.75 r0 top
C122 "C0603C104J3RACTU" 0603#1 1885,1339.75 r0 top
C259 "C0603C104J3RACTU" 0603#1 4177.01,2166.39 r0 bottom
C260 "C0603C104J3RACTU" 0603#1 4175.03,526.69 r0 bottom
C261 "GRM21BR71A106KE51L" 0805_HV 4015.02,681.69 r270 bottom
C262 "GRM21BR71A106KE51L" 0805_HV 4012.01,2356.39 r270 bottom
C266 "C0603C104J3RACTU" 0603#1 3932.01,2221.39 r0 bottom
C267 "C0603C104J3RACTU" 0603#1 4167.01,2751.39 r0 bottom
C268 "C0603C104J3RACTU" 0603#1 3940.02,576.69 r0 bottom
C269 "C0603C104J3RACTU" 0603#1 4175.03,1111.71 r0 bottom
C271 "GRM21BR71A106KE51L" 0805_HV 3997,2656.4 r90 bottom
C272 "GRM21BR71A106KE51L" 0805_HV 4000.02,976.69 r90 bottom
C284 "GRM21BR71A106KE51L" 0805_HV 1485,2139.75 r0 top
C287 "GRM21BR71A106KE51L" 0805_HV 1925,2099.75 r180 top
C288 "GRM21BR71A106KE51L" 0805_HV 2135,2084.75 r0 top
C289 "GRM21BR71A106KE51L" 0805_HV 2125,2544.75 r0 top
C290 "GRM21BR71A106KE51L" 0805_HV 3235,2355.04 r90 top
C291 "GRM21BR71A106KE51L" 0805_HV 2852.81,2603.54 r180 top
C304 "GRM21BR71A106KE51L" 0805_HV 1525,884.75 r90 top
C305 "GRM21BR71A106KE51L" 0805_HV 1525,1189.75 r90 top
C306 "GRM21BR71A106KE51L" 0805_HV 1700,949.75 r180 top
C307 "GRM21BR71A106KE51L" 0805_HV 1910,934.75 r0 top
C308 "GRM21BR71A106KE51L" 0805_HV 1890,1409.75 r0 top
C315 "C1608C0G2A102J080AA" 0603#1 1895,2314.75 r90 top
C316 "C1608C0G2A102J080AA" 0603#1 1330,2254.75 r90 top
C317 "C1608C0G2A102J080AA" 0603#1 1330,2374.75 r270 top
C318 "GRM188R71E105KA12D" 0603#1 1220,1737.38 r180 top
C319 "GRM188R71E105KA12D" 0603#1 1030,1737.38 r180 top
C320 "C0603C104J3RACTU" 0603#1 875,1829.75 r270 top
C321 "GRM188R71E105KA12D" 0603#1 1125,1852.38 r270 top
C322 "C1608X5R1A226M080AC" 0603#1 1990,2484.75 r90 top
C323 "C1608X5R1A226M080AC" 0603#1 1765,1334.75 r90 top
C335 "CGA3E2C0G1H103J080AA" 0603#1 1670,1165.75 r90 top
C338 "GRM21BR71A106KE51L" 0805_HV 2670,2026.65 r90 top
C339 "GRM188R71E105KA12D" 0603#1 2820,2029.75 r270 top
C340 "GRM155R71C104KA88D" 0402 2870,2029.75 r270 top
C343 "GRM21BR71A106KE51L" 0805_HV 2855.21,1264.75 r90 top
C344 "GRM155R71C104KA88D" 0402 2790.21,1264.75 r270 top
C345 "GRM21BR71A106KE51L" 0805_HV 2459.83,1471.28 r180 top
C346 "GRM155R71C104KA88D" 0402 2459.83,1406.28 r180 top
C347 "GRM21BR71A106KE51L" 0805_HV 3225,2355.04 r90 bottom
C348 "GRM188R71E105KA12D" 0603#1 3040,2149.75 r180 bottom
C349 "GRM155R71C104KA88D" 0402 3053.55,2089.75 r180 bottom
C350 "GRM155R71C104KA88D" 0402 3053.55,2044.75 r180 bottom
C351 "293D475X9025C2TE3" 6032-28 1975,3180 r90 bottom
C352 "293D475X9025C2TE3" 6032-28 3145,2770 r0 bottom
C353 "293D475X9025C2TE3" 6032-28 2140,370 r90 bottom
C354 "UMK325AB7106KM-T" 1210_280 2405,3170 r0 bottom
C355 "C2012X7R2A104K125AA" 0805_HV 491,505 r90 bottom
C356 "C3216X7R1V475K085AC" 1206 587,487 r90 bottom
C357 "GRM31CR71E106KA12L" 1206_180 1180,585 r0 bottom
C358 "GRM31CR71E106KA12L" 1206_180 1185,125 r0 bottom
C359 "C2012X7R2A104K125AA" 0805_HV 1180,495 r0 bottom
C360 "C2012X7R2A104K125AA" 0805_HV 1180,215 r0 bottom
C361 "GCM188R71E474KA64D" 0603#1 1035,495 r0 bottom
C362 "C1005X6S1H104K050BB" 0402 910,375 r270 bottom
C363 "C0402C101J3GACTU" 0402 920,165 r270 bottom
C364 "CGA6P1X7R1C226M250AC" 1210_280 1470,455 r90 bottom
C366 "CGA6P1X7R1C226M250AC" 1210_280 1470,255 r270 bottom
C367 "C2012X7R2A104K125AA" 0805_HV 4095,3565 r0 bottom
C368 "C3216X7R1V475K085AC" 1206 4114.41,3470 r0 bottom
C369 "GRM31CR71E106KA12L" 1206_180 3485,3350 r180 bottom
C370 "GRM31CR71E106KA12L" 1206_180 3480,3810 r180 bottom
C371 "C2012X7R2A104K125AA" 0805_HV 3485,3440 r180 bottom
C372 "C2012X7R2A104K125AA" 0805_HV 3485,3720 r180 bottom
C373 "GCM188R71E474KA64D" 0603#1 3630,3440 r180 bottom
C374 "C0402C101J3GACTU" 0402 3745,3770 r90 bottom
C375 "C1005X6S1H104K050BB" 0402 3755,3560 r90 bottom
C376 "CGA6P1X7R1C226M250AC" 1210_280 3200,3470 r270 bottom
C378 "CGA6P1X7R1C226M250AC" 1210_280 3200,3670 r90 bottom
C379 "C2012X7R2A104K125AA" 0805_HV 715,3735 r90 bottom
C380 "C3216X7R1V475K085AC" 1206 620,3755 r90 bottom
C381 "GRM31CR71E106KA12L" 1206_180 1022.8,3320 r0 bottom
C382 "GRM31CR71E106KA12L" 1206_180 1030,2860 r0 bottom
C383 "C2012X7R2A104K125AA" 0805_HV 1020,3230 r0 bottom
C384 "C2012X7R2A104K125AA" 0805_HV 1010,2950 r0 bottom
C385 "GCM188R71E474KA64D" 0603#1 875,3230 r0 bottom
C387 "C0402C101J3GACTU" 0402 760,2900 r270 bottom
C388 "C1005X6S1H104K050BB" 0402 750,3110 r270 bottom
C389 "UMK325AB7106KM-T" 1210_280 1305,2935 r270 bottom
C391 "UMK325AB7106KM-T" 1210_280 1305,3245 r90 bottom
C401 "C3225X7S1H106K250AB" 1210_280 2000,3621.5 r90 bottom
C402 "C1608X5R1H104K080AA" 0603#1 2100,3605 r90 bottom
C403 "GRM188R61E475KE11D" 0603#1 2650,3550 r0 bottom
C404 "C1608X5R1H474K080AB" 0603#1 2610,3645 r90 bottom
C405 "C1608X7R1V105K080AC" 0603#1 2650,3485 r0 bottom
C406 "C3216X5R1V226M160AC" 1206_180 2295,3760 r270 bottom
C407 "C0603C223K3RACTU" 0603#1 2180,3495 r180 bottom
C408 "UMK325AB7106KM-T" 1210_280 2195,3620 r90 bottom
C409 "C0603C470J5GACTU" 0603#1 2180,3365 r0 bottom
C449 "ZRB18AD71A106KE01L" 0603_120#1 589.83,1679.02 r0 top
C452 "0805YC224JAT2A" 0805_HV 450,1749.75 r0 top
C453 "GRM188R71E105KA12D" 0603#1 945,1534.75 r270 top
C454 "C0603C104J3RACTU" 0603#1 810,1739.75 r0 top
C455 "C0603C104J3RACTU" 0603#1 810,1429.75 r180 top
C457 "ZRB18AD71A106KE01L" 0603_120#1 445,1919.75 r0 top
C458 "ZRB18AD71A106KE01L" 0603_120#2 445,1814.75 r0 top
C459 "ZRB18AD71A106KE01L" 0603_120#1 445,1869.75 r0 top
C460 "C0603C104J3RACTU" 0603#1 710,1509.75 r90 top
C461 "C0603C100F5GAC7867" 0603#1 404.7,1580 r270 top
Cff "C1608X7R2A223K080AA" 0603#1 875,3245 r270 top
Cff2 "08055C223KAT2A" 0805_HV 3295,3325 r180 top
Cff3 "08055C223KAT2A" 0805_HV 2466,166 r180 top
Cin "UMK325AB7106KM-T" 1210_280 1475,3570 r90 bottom
Cin1 "UMK325AB7106KM-T" 1210_280 610,2835 r180 top
Cin2 "UMK325AB7106KM-T" 1210_280 3479.71,3829.96 r0 top
Cin3 "UMK325AB7106KM-T" 1210_280 2680,700 r0 top
CMFB "GRM1885C2A680JA01D" 0603#1 1165,2314.75 r90 top
Cout1 "C2012JB1V226M125AC" 0805_HV 955,3235 r270 top
Cout2 "UMK325AB7106KM-T" 1210_280 601,3376 r180 top
Cout3 "C2012X7S2A105K125AB" 0805_HV 1040,3235 r270 top
Cout4 "C3216X5R1E476M160AC" 1206_190 3505,3260 r0 top
Cout5 "C3225X6S0J107M250AC" 1210_280 2654,95 r0 top
Cout6 "C0603C105K3RACTU" 0603#1 2624,180 r0 top
Css "CGA3E2X7R2A472K080AA" 0603#1 820,3125 r90 top
Css2 "GRM188R70J103KA01D" 0603#1 3235,3495 r180 top
Css3 "GRM188R70J103KA01D" 0603#1 2331,352 r180 top
CVCC3V "GCM188R70J225KE22D" 0603#1 970,395 r270 bottom
CVCC5V "GCM188R70J225KE22D" 0603#1 3695,3540 r90 bottom
CVCC18V "GCM188R70J225KE22D" 0603#1 810,3130 r270 bottom
D1 "MBRS4201T3G" SMC 1205,3450 r180 top
D2 "DFLS1100-7" PowerDI123 2315,3764 r270 top
D14 "150060RS75000" WL-SMCW_RED 2320,170 r180 top
D18 "150060RS75000" WL-SMCW_RED 2486,2713 r90 top
D21 "150060RS75000" WL-SMCW_RED 2783.32,3188.24 r90 top
D22 "150060RS75000" WL-SMCW_RED 2040,2990 r90 top
FDA1 "THS4551IRGTR" RGT0016A 1440,2314.75 r0 top
FID1 "Fiducial" Fiducial10-20 4298,522 r0 top
FID2 "Fiducial" Fiducial10-20 268,467 r0 top
FID3 "Fiducial" Fiducial10-20 4309,3509 r0 top
FID4 "Fiducial" Fiducial10-20 4298,522 r180 bottom
FID5 "Fiducial" Fiducial10-20 268,467 r180 bottom
FID6 "Fiducial" Fiducial10-20 4309,3509 r180 bottom
GNDin "5015" Testpoint_Keystone_Miniature 1560,3825 r0 top
H1 "NY PMS 440 0025 PH" "NY PMS 440 0025 PH" 4277,3765 r0 top locked
H2 "NY PMS 440 0025 PH" "NY PMS 440 0025 PH" 260,3761 r0 top locked
H3 "NY PMS 440 0025 PH" "NY PMS 440 0025 PH" 4278,275 r0 top locked
H4 "NY PMS 440 0025 PH" "NY PMS 440 0025 PH" 268,206 r0 top locked
H5 "1902C" Keystone_1902C 4277,3765 r180 bottom locked
H6 "1902C" Keystone_1902C 259.47,3761 r180 bottom locked
H7 "1902C" Keystone_1902C 4278,275 r180 bottom locked
H8 "1902C" Keystone_1902C 268,206 r180 bottom locked
H9 "9774050360R" Wurth_WA-SMSI 3880.02,176.69 r180 top
H11 "9774050360R" Wurth_WA-SMSI 3880.02,1476.69 r180 top
H13 "9774050360R" Wurth_WA-SMSI 3872.01,3116.39 r180 top
H15 "9774050360R" Wurth_WA-SMSI 3872.01,1816.39 r180 top
J3 "61300311121" WURTH_61300311121 2935,1399.75 r0 top
J4 "QTH-030-01-L-D-A" Samtec_QTH-030-01-x-D-A 4042.01,2466.39 r270 top
J5 "61300211121" WURTH_61300211121 3707,2854.4 r180 top
J6 "61300211121" WURTH_61300211121 3718.34,441.75 r180 top
J7 "QTH-030-01-L-D-A" Samtec_QTH-030-01-x-D-A 4050.02,826.69 r270 top
J8 "691213710002" Wurth_691213710002 1220,3745 r180 top
J14 "901-144-8RFX" Amphenol_901-144-8RFX 465,2169 r90 top
J15 "901-144-8RFX" Amphenol_901-144-8RFX 465,2588 r90 top
J18 "901-144-8RFX" Amphenol_901-144-8RFX 465,909 r90 top
J19 "901-144-8RFX" Amphenol_901-144-8RFX 465,1328 r90 top
J37 "TMM-103-01-G-S-SM" Samtec_TMM-103-01-x-S-SM 3350,2524.75 r270 top
J38 "TMM-103-01-G-S-SM" Samtec_TMM-103-01-x-S-SM 2695,1084.75 r270 top
J39 "TMM-103-01-G-S-SM" Samtec_TMM-103-01-x-S-SM 2623.02,573 r270 bottom
JMTI_-18V "61300211121" WURTH_61300211121 1765,3865 r0 top
JPRI_-18V "61300211121" WURTH_61300211121 2824,3802 r90 bottom
JSI_3.3V "61300211121" WURTH_61300211121 582,275 r270 bottom
JSI_5V "61300211121" WURTH_61300211121 4044,3815 r90 bottom
JSI_18V "61300211121" WURTH_61300211121 655,3540 r90 bottom
JTI_3.3V "TMM-103-01-G-S-SM" Samtec_TMM-103-01-x-S-SM 1460,165 r0 top
JTI_5V "TMM-103-01-G-S-SM" Samtec_TMM-103-01-x-S-SM 3335,3130 r90 top
JTI_18V "TMM-103-01-G-S-SM" Samtec_TMM-103-01-x-S-SM 1455,3155 r90 top
JTI_-18V "TMM-103-01-G-S-SM" Samtec_TMM-103-01-x-S-SM 2380,3315 r270 top
JZI_3.3V "61300211121" WURTH_61300211121 2410,765 r180 top
JZI_5V "61300211121" WURTH_61300211121 3304,3826 r90 top
JZI_18V "61300211121" WURTH_61300211121 321,2846 r180 bottom
L1 "DR73-331-R" DR73 2554,3765 r0 top
L4 "MPZ2012S601A" 0805_HV 3058.02,473 r90 bottom
L5 "MPZ2012S601A" 0805_HV 2995,785 r0 bottom
L6 "MPZ2012S601A" 0805_HV 1700,869.75 r0 top
L7 "MPZ2012S601A" 0805_HV 1910,854.75 r180 top
L8 "MPZ2012S601A" 0805_HV 1925,2019.75 r0 top
L9 "MPZ2012S601A" 0805_HV 2135,2004.75 r180 top
L10 "MPZ2012S601A" 0805_HV 2750,2026.65 r270 top
L12 "MPZ2012S601A" 0805_HV 3060,2259.75 r90 bottom
L16 "MPZ2012S601A" 0805_HV 1515,3085 r180 bottom
L17 "MPZ2012S601A" 0805_HV 2270,3215 r90 bottom
L18 "MPZ2012S601A" 0805_HV 3020,3220 r180 bottom
L19 "MPZ2012S601A" 0805_HV 1555,65 r0 bottom
L20 "NR3015T3R3M" NR3015 702,403 r0 bottom
L21 "TYS30154R7M-10" TYS3015 1325,355 r0 bottom
L22 "NR3015T3R3M" NR3015 4010,3350 r180 bottom
L23 "744025006" WE-TPC_2828 3340,3570 r180 bottom
L24 "NR3015T3R3M" NR3015 805,3460 r270 bottom
L25 "744025006" WE-TPC_2828 1165,3090 r0 bottom
L401 "744031680" WE-TPC_3816 2470,3825 r180 bottom
Logo1 "Texas Instruments" TI_Stacked_Overlay_Small 3319,110 r0 top
Logo2 "Pb-Free Symbol" Pb-Free_Overlay_Small 4085,62 r0 top
NT1 "Net-Tie" Net-Tie_50milWide_30milLong 2141.69,2314.75 r0 top net-tie
NT2 "Net-Tie" Net-Tie_50milWide_30milLong 1920,1161 r0 top net-tie
OPAN_1 "OPA827AIDR" D0008A_N 904.99,2189.74 r0 top
OPAN_2 "OPA827AIDR" D0008A_N 905,989.75 r0 top
OPAP_1 "OPA827AIDR" D0008A_N 905,2489.75 r0 top
OPAP_2 "OPA827AIDR" D0008A_N 905,1289.75 r0 top
R3 "ERJ-3RQFR22V" 0603#1 1420,1805.16 r0 top
R4 "ERJ-3RQFR22V" 0603#1 1730,1954.75 r180 top
R8 "ERJ-2GE0R00X" 0402 2010,2880 r180 top
R9 "ERJ-2GE0R00X" 0402 2010,2835 r180 top
R10 "ERJ-2GE0R00X" 0402 1800,2865 r90 top
R11 "ERJ-2GE0R00X" 0402 1755,2865 r90 top
R12 "ERJ-2GE0R00X" 0402 1710,2865 r90 top
R13 "ERJ-2GE0R00X" 0402 1665,2865 r90 top
R14 "ERJ-2GE0R00X" 0402 1620,2865 r90 top
R15 "ERJ-2GE0R00X" 0402 1575,2865 r90 top
R17 "ERJ-2GE0R00X" 0402 2710,2855 r0 top
R18 "ERJ-2GE0R00X" 0402 2710,2895 r0 top
R19 "ERJ-2GE0R00X" 0402 2710,2935 r0 top
R20 "ERJ-2GE0R00X" 0402 2710,2975 r0 top
R21 "CRCW06030000Z0EA" 0603#1 3178.02,328 r180 bottom
R22 "RT0603DRE074R7L" 0603#1 3148.02,783 r180 bottom
R24 "ERJ-2GE0R00X" 0402 2710,3015 r0 top
R25 "ERJ-2GE0R00X" 0402 2710,3055 r0 top
R26 "ERJ-2GE0R00X" 0402 2855,3200 r270 top
R27 "ERJ-2GE0R00X" 0402 2906,3200 r270 top
R29 "ERJ-2GE0R00X" 0402 2200,80 r180 top
R30 "ERJ-2GE0R00X" 0402 2200,40 r180 top
R31 "ERJ-2GE0R00X" 0402 1985,300 r270 top
R32 "ERJ-2GE0R00X" 0402 1940,300 r270 top
R33 "ERJ-2GE0R00X" 0402 1900,300 r270 top
R34 "ERJ-2GE0R00X" 0402 1860,300 r270 top
R35 "ERJ-2GE0R00X" 0402 1820,300 r270 top
R36 "ERJ-2GE0R00X" 0402 1780,300 r270 top
R40 "RT0603BRD07215KL" 0603#1 1670.02,3587.8 r180 top
R41 "RG1608P-2322-B-T5" 0603#1 1670,3470 r180 top
R42 "RG1608P-1651-B-T5" 0603#1 1795,3465 r180 top
R43 "RG1608P-3092-B-T5" 0603#1 2680,3108.05 r90 bottom
R44 "RT0603BRD072K15L" 0603#1 2680,2983.05 r90 bottom
R45 "RT0603BRD0752K3L" 0603#1 1960,3855 r180 top
R46 "RC0603JR-07910RL" 0603#1 2205,170 r180 top
R47 "RT0603BRD0718KL" 0603#1 2585,2745 r0 top
R50 "RG1608P-203-B-T5" 0603#1 1952.22,3527.56 r90 top
R56 "ERJ-2GE0R00X" 0402 1945,1769.75 r0 top
R64 "CRCW060310K0FKEA" 0603#1 4227.01,2451.39 r90 bottom
R65 "ERJ-2GE0R00X" 0402 3737.74,2756.39 r0 top
R66 "ERJ-2GE0R00X" 0402 3737.74,2711.39 r0 top
R67 "ERJ-2GE0R00X" 0402 3737.74,2666.39 r0 top
R68 "ERJ-2GE0R00X" 0402 3737.74,2621.39 r0 top
R69 "ERJ-2GE0R00X" 0402 3737.74,2576.39 r0 top
R70 "ERJ-2GE0R00X" 0402 3737.74,2531.39 r0 top
R71 "ERJ-2GE0R00X" 0402 3737.74,2486.39 r0 top
R72 "ERJ-2GE0R00X" 0402 3737.74,2441.39 r0 top
R73 "ERJ-2GE0R00X" 0402 3737.74,2396.39 r0 top
R74 "ERJ-2GE0R00X" 0402 3737.74,2351.39 r0 top
R75 "ERJ-2GE0R00X" 0402 3737.74,2306.39 r0 top
R76 "ERJ-2GE0R00X" 0402 3730.03,1116.69 r0 top
R77 "ERJ-2GE0R00X" 0402 3730.03,1071.69 r0 top
R78 "ERJ-2GE0R00X" 0402 3730.03,1026.69 r0 top
R79 "ERJ-2GE0R00X" 0402 3730.03,981.69 r0 top
R80 "ERJ-2GE0R00X" 0402 3730.03,936.69 r0 top
R81 "ERJ-2GE0R00X" 0402 3730.03,891.69 r0 top
R82 "ERJ-2GE0R00X" 0402 3730.03,846.69 r0 top
R83 "ERJ-2GE0R00X" 0402 3730.03,801.69 r0 top
R84 "ERJ-2GE0R00X" 0402 3730.03,756.69 r0 top
R85 "ERJ-2GE0R00X" 0402 3730.03,711.69 r0 top
R86 "ERJ-2GE0R00X" 0402 3730.03,666.69 r0 top
R87 "CRCW060310K0FKEA" 0603#1 4220.03,766.7 r90 bottom
R88 "CRCW04024K70JNED" 0402 2960,1514.75 r90 top
R89 "CRCW04024K70JNED" 0402 3005,1514.75 r90 top
R90 "CRCW04024K70JNED" 0402 3080,1589.75 r180 top
R91 "CRCW04024K70JNED" 0402 2985,1589.75 r0 top
R92 "CRCW0402100RJNED" 0402 3040,1969.75 r0 top
R95 "CRCW040233R0JNED" 0402 3265,2199.75 r0 top
R97 "RG1608P-103-B-T5" 0603#1 676,2197 r270 top
R98 "RG1608P-103-B-T5" 0603#1 676,2497 r270 top
R99 "CRCW0603249RFKEA" 0603#1 1270,2254.75 r270 top
R100 "RC0603FR-07499RL" 0603#1 1715,2249.75 r90 top
R101 "RC0603FR-07499RL" 0603#1 1715,2379.75 r270 top
R103 "RT0603BRD0720RL" 0603#1 1805,2279.75 r0 top
R104 "RT0603BRD0720RL" 0603#1 1805,2349.75 r0 top
R107 "RG1608P-103-B-T5" 0603#1 676,1000 r270 top
R108 "RG1608P-103-B-T5" 0603#1 675.7,1237 r90 top
R110 "RG1608P-202-B-T5" 0603#1 1170,904.75 r0 bottom
R111 "RG1608P-202-B-T5" 0603#1 1050,904.75 r0 bottom
R112 "RC0603FR-0730RL" 0603#1 1235,1394.75 r180 top
R113 "RC0603FR-0730RL" 0603#1 1235,1069.75 r180 top
R114 "RC0603FR-07499RL" 0603#1 1355,1069.75 r0 top
R115 "RT0603BRD0720RL" 0603#1 1475,1014.75 r0 top
R116 "RC0603FR-07499RL" 0603#1 1355,1394.75 r0 top
R117 "RT0603BRD0720RL" 0603#1 1475,1339.75 r0 top
R211 "ERJ-2GE0R00X" 0402 1575,2289.75 r0 top
R212 "ERJ-2GE0R00X" 0402 1575,2339.75 r0 top
R213 "ERJ-2GE0R00X" 0402 1170,959.75 r0 bottom
R214 "RG1608P-4990-B-T5" 0603#1 1220,1682.38 r0 top
R215 "RG1608P-4990-B-T5" 0603#1 1125,1707.38 r270 top
R216 "RG1608P-203-B-T5" 0603#1 1030,1682.38 r0 top
R217 "RG1608P-4992-B-T5" 0603#1 1180,1852.38 r90 top
R218 "RG1608P-4992-B-T5" 0603#1 1235,1852.38 r270 top
R223 "ERJ-2GE0R00X" 0402 2075,874.75 r0 top
R225 "ERJ-2GE0R00X" 0402 2075,1054.75 r0 top
R226 "ERJ-2GE0R00X" 0402 2075,1145 r0 top
R232 "ERJ-2GE0R00X" 0402 2335,2169.75 r0 top
R233 "ERJ-2GE0R00X" 0402 2335,2214.75 r0 top
R234 "ERJ-2GE0R00X" 0402 2335,2259.75 r0 top
R235 "ERJ-2GE0R00X" 0402 2335,2304.75 r0 top
R240 "ERJ-2GE0R00X" 0402 2075,1009.75 r0 top
R246 "RG1608P-4992-B-T5" 0603#1 2785,3305 r90 top
R247 "RG1608P-4992-B-T5" 0603#1 2040,3114.02 r90 top
R248 "ERJ-2GE0R00X" 0402 1480,2454.75 r0 top
R250 "ERJ-2GE0R00X" 0402 1395,934.75 r270 bottom
R252 "ERJ-2GE0R00X" 0402 1394.48,1244.01 r270 bottom
R255 "ERJ-2GE0R00X" 0402 1995,1654.75 r180 top
R256 "CRCW040233R0JNED" 0402 3265,2149.75 r0 top
R257 "CRCW040233R0JNED" 0402 3265,2094.75 r0 top
R258 "RG1608P-103-B-T5" 0603#1 2125,2614.75 r0 top
R259 "ERJ-2GE0R00X" 0402 2130,2664.75 r0 top
R260 "ERJ-2GE0R00X" 0402 2130,2709.75 r0 top
R261 "RG1608P-103-B-T5" 0603#1 1885,1479.75 r0 top
R262 "ERJ-2GE0R00X" 0402 1890,1529.75 r180 top
R263 "ERJ-2GE0R00X" 0402 1890,1574.75 r180 top
R268 "CRCW06031R00FKEA" 0603#1 1935,2514.75 r90 top
R269 "CRCW06031R00FKEA" 0603#1 1710,1359.75 r90 top
R278 "CRCW040233R0JNED" 0402 3265,2044.75 r0 top
R279 "ERJ-2GE0R00X" 0402 4122.01,2406.39 r0 bottom
R280 "ERJ-2GE0R00X" 0402 4130.02,731.69 r0 bottom
R284 "ERJ-2GE0R00X" 0402 1915,2429.75 r0 top
R288 "ERJ-2GE0R00X" 0402 1690,1274.75 r0 top
R290 "CRCW040236K0JNED" 0402 920,270 r270 bottom
R291 "CRCW0402100KFKED" 0402 865,165 r90 bottom
R294 "CRCW040222K6FKED" 0402 3745,3665 r90 bottom
R295 "CRCW0402100KFKED" 0402 3800,3770 r270 bottom
R297 "PCF0402-12-5K62BT1" 0402 745,3005 r270 bottom
R298 "CRCW0402100KFKED" 0402 705,2900 r90 bottom
R401 "CRCW06031K00FKEA" 0603#2 325,1665 r0 bottom
R402 "RT0603BRD0717K2L" 0603#1 2180,3430 r0 bottom
R404 "CRCW060380K6FKEA" 0603#1 2500,3395 r0 bottom
R453 "ERJ-2GE0R00X" 0402 675,1629.75 r270 top
R454 "ERJ-2GE0R00X" 0402 720,1629.75 r270 top
R457 "ERJ-2GE0R00X" 0402 495,1979.75 r0 top
R485 "RG1608P-102-B-T5" 0603#1 1000,1534.75 r90 top
R486 "RG1608P-2491-B-T5" 0603#1 810,1629.75 r180 top
R488 "RG1608P-4991-B-T5" 0603#1 810,1684.75 r180 top
R489 "CRCW06034R75FKEA" 0603#1 460,1674.75 r180 top
R491 "RG1608P-102-B-T5" 0603#1 459.7,1579.75 r270 top
R492 "RG1608P-4990-B-T5" 0603#1 349.7,1580 r90 top
R494 "RG1608P-303-B-T5" 0603#1 289.7,1580 r90 top
RB3 "ERJ-2GE0R00X" 0402 910,480 r90 bottom
RB5 "ERJ-2GE0R00X" 0402 3755,3455 r270 bottom
RB18 "ERJ-2GE0R00X" 0402 750,3215 r90 bottom
RDN1 "RG1608P-202-B-T5" 0603#1 1120,2464.75 r0 top
RDN2 "RG1608P-202-B-T5" 0603#1 1240,2464.75 r0 top
RDN3 "RG1608P-202-B-T5" 0603#1 1114.69,1264.75 r0 top
RDN4 "RG1608P-202-B-T5" 0603#1 1234.69,1284.75 r0 top
RDP1 "RG1608P-202-B-T5" 0603#1 1120,2164.75 r0 top
RDP2 "RG1608P-202-B-T5" 0603#1 1240,2164.75 r0 top
RDP3 "RG1608P-202-B-T5" 0603#1 1115,959.75 r0 top
RDP4 "RG1608P-202-B-T5" 0603#1 1235,959.75 r0 top
REN0 "ERJ-2GE0R00X" 0402 1380,779.75 r180 top
REN1 "ERJ-2GE0R00X" 0402 1375,1119.75 r180 top
Renb "CRCW080520K5FKEA" 0805_HV 930,2850 r180 top
Renb2 "RG1608P-3571-B-T5" 0603#1 3080,3705 r0 top
Renb3 "RG1608P-3571-B-T5" 0603#1 2246,624 r0 top
Rent "RT0805BRD07118KL" 0805_HV 775,2850 r180 top
Rent2 "RT0603BRD0768K1L" 0603#1 3200,3705 r0 top
Rent3 "RT0603BRD0768K1L" 0603#1 2375,625 r0 top
RES3V "RG1608P-104-B-T5" 0603#1 980,225 r90 bottom
RES5V "RG1608P-104-B-T5" 0603#1 3685,3710 r270 bottom
RES18V "RG1608P-104-B-T5" 0603#1 820,2960 r90 bottom
Rfbb "RG1608P-152-B-T5" 0603#1 880,3120 r90 top
Rfbb3 "RT0805BRD071K07L" 0805_HV 2312,246 r0 top
Rfbb5 "RT0805BRD071K07L" 0805_HV 3095,3500 r270 top
Rfbt "RT0603BRD0734KL" 0603#1 815,3245 r90 top
Rfbt2 "CPF0603B6K34E" 0603#1 3280,3400 r0 top
Rfbt3 "RG1608P-4021-B-T5" 0603#1 2455,245 r0 top
RMFBN "ERJ-2GE0R00X" 0402 1245,2524.75 r0 top
RMFBP "ERJ-2GE0R00X" 0402 1245,2104.75 r180 top
Ron "RT0603BRD07383KL" 0603#1 800,2980 r270 top
Ron2 "RT0603BRD07113KL" 0603#1 3285,3660 r180 top
Ron3 "RT0603BRD0778K7L" 0603#1 2484,578 r90 top
TP1 "Pogo Pad" PogoPad 2400,2484.75 r0 top
TP2 "Pogo Pad" PogoPad 3125,2515.04 r0 top
TP3 "5015" Testpoint_Keystone_Miniature 1850,3250 r0 top
TP4 "Pogo Pad" PogoPad 2540,1099.75 r0 top
TP7 "Pogo Pad" PogoPad 2867.81,2298.54 r0 top
TP8 "5015" Testpoint_Keystone_Miniature 1400,1949.75 r270 top
TP16 "Pogo Pad" PogoPad 3385,2259.75 r0 top
TP25 "5015" Testpoint_Keystone_Miniature 2215,3030 r0 top
TP26 "5015" Testpoint_Keystone_Miniature 2670,3173.05 r180 top
TP27 "5015" Testpoint_Keystone_Miniature 3050,785 r0 top
TP28 "5015" Testpoint_Keystone_Miniature 1180,1970 r0 top
TP29 "5015" Testpoint_Keystone_Miniature 1180,1582.38 r0 top
TP30 "5015" Testpoint_Keystone_Miniature 1115,819.75 r180 bottom
TP31 "Pogo Pad" PogoPad 3385,2169.75 r0 top
TP32 "Pogo Pad" PogoPad 3385,2069.75 r0 top
TP33 "Pogo Pad" PogoPad 3385,1969.75 r0 top
TP34 "Pogo Pad" PogoPad 2720,1439.75 r90 top
TP35 "Pogo Pad" PogoPad 2460.3,1166.28 r90 top
TP_3P3V "5015" Testpoint_Keystone_Miniature 2130,325 r90 top
TP_3P8V "5015" Testpoint_Keystone_Miniature 1656,221 r90 top
TP_5P5V "5015" Testpoint_Keystone_Miniature 2915,3454.51 r90 top
TP_18P5V "5015" Testpoint_Keystone_Miniature 1621,3233 r0 top
TPAGND "Pogo Pad" PogoPad 2065,1859.75 r90 top locked
TPAGND1 "5015" Testpoint_Keystone_Miniature 1625,2692.75 r0 top
TPAGND2 "5015" Testpoint_Keystone_Miniature 1590,1584.75 r270 top
TPAGND3 "5015" Testpoint_Keystone_Miniature 990,1949.75 r180 top
TPAGND4 "5015" Testpoint_Keystone_Miniature 1116.5,819.75 r0 top
TPGND "Pogo Pad" PogoPad 2613,1819.75 r90 top
TPGND1 "5015" Testpoint_Keystone_Miniature 3378.02,408 r90 top
TPGND2 "5015" Testpoint_Keystone_Miniature 2450,1779.75 r90 top
TPGND3 "5015" Testpoint_Keystone_Miniature 3540,2990 r180 top
TPGND4 "5015" Testpoint_Keystone_Miniature 3490,395 r90 top
TPPGOOD "Pogo Pad" PogoPad 2795,3435 r270 bottom
U1 "OPA625IDBVR" DBV0006A_N 1355,894.75 r270 top
U2 "OPA625IDBVR" DBV0006A_N 1355,1224.75 r270 top
U3 "REF6041IDGKR" DGK0008A_N 1620,1805.16 r0 top
U3P8V "LMS3635MQRNLRQ1" RNL0022A_NV 1130,355 r270 bottom
U4 "OPA376AIDBVR" DBV0005A_N 995,1835.01 r180 top
U5 "LMZ14202TZX-ADJ/NOPB" TZA07A_V 2793,429 r0 top
U5P5V "LMS3635MQRNLRQ1" RNL0022A_NV 3535,3580 r90 bottom
U6 "TPS7A4700RGWR" RGW0020A 1910,185 r180 bottom
U7 "TPS7A4700RGWR" RGW0020A 2905,2980 r90 bottom
U8 "TPS7A4700RGWR" RGW0020A 1740,3040 r180 bottom
U9 "LM5574MT" MTC16_N 2125,3695 r0 top
U10 "LM7705MM/NOPB" MUA08A_N 3173.02,498 r90 bottom
U11 "TPS7A3001MDGNTEP" DGN0008D_N 2520,3050 r180 bottom
U13 "BR24G32FVT-3AGE2" TSOP65P640X120-8N 4032.01,2506.39 r180 bottom
U14 "BR24G32FVT-3AGE2" TSOP65P640X120-8N 4035.02,831.69 r180 bottom
U15 "LMK61E2-SIAR" SIA0008B 2990,1729.75 r90 top
U18 "SN74AUP1G80DCKR" DCK0005A_N 3097.81,2378.54 r270 top
U18P5V "LMS3635MQRNLRQ1" RNL0022A_NV 970,3090 r270 bottom
U19 "SN74AHC1G04DBVR" DBV0005A_N 2867.81,2428.54 r90 top
U22 "LMZ14201TZX-ADJ/NOPB" TZA07A_V 509,3108 r180 top
U23 "LMZ14203TZ-ADJ/NOPB" TZA07A_V 3605,3560 r0 top
U31 "SN74AUP1G80DCKR" DCK0005A_N 2715.21,1284.75 r270 top
U32 "SN74AHC1G04DBVR" DBV0005A_N 2459.83,1296.28 r90 top
U33 "LMK00804BPW" PW0016A_N 3050,2109.75 r0 top
U401 "LM46001PWPR" PWP0016G_N 2405,3550 r180 bottom
U414 "OPA378AIDBVT" DBV0005A_N 830,1529.75 r180 top
U415 "OPA625IDBVR" DBV0006A_N 570,1579.75 r0 top
UADS1 "ADS8900BRGER" RGE0024H 2060,2314.75 r270 top
UADS2 "ADS8900BRGER" RGE0024H 1835,1164.75 r270 top
ZZ2 "These assemblies are ESD sensitive, ESD precautions shall be observed." AssemblyNote 300,4700 r0 top
ZZ3 "These assemblies must be clean and free from flux and all contaminants. Use of no clean flux is not acceptable." AssemblyNote 300,4600 r0 top
ZZ4 "These assemblies must comply with workmanship standards IPC-A-610 Class 2, unless otherwise specified." AssemblyNote 300,4500 r0 top

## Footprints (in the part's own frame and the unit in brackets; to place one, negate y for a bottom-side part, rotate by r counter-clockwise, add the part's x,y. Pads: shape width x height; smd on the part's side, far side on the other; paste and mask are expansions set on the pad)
0402 [mm] "0402 from SM-752 data"
  rect 0.8x0.6 smd: 1(-0.6,0) 2(0.6,0)
  silkscreen extent -1.22,-0.52 1.22,0.52, body extent -0.55,-0.3 0.55,0.3, height 0.6
0603#1 [mm] "0603 from SM-752 data"
  rect 1x0.95 smd: 1(-0.8,0) 2(0.8,0)
  silkscreen extent -1.52,-0.69 1.52,0.69, body extent -0.87,-0.47 0.87,0.47, height 1
0603#2 [mm] "0603 from SM-752 data"
  rect 1x0.95 smd: 1(50.97,-44.274) 2(52.57,-44.274)
  silkscreen extent 50.25,-44.96 53.29,-43.58, body extent 50.9,-44.75 52.64,-43.8, height 1
0603_120#1 [mm] "0603_120"
  rect 1x1 smd: 1(-0.8,0) 2(0.8,0)
  silkscreen extent -0.1,-0.58 0.1,0.58, body extent -0.87,-0.48 0.87,0.48, height 1.2
0603_120#2 [mm] "0603_120"
  rect 1x1 smd: 1(-0.8,0.127) 2(0.8,0.127)
  silkscreen extent -0.1,-0.45 0.1,0.7, body extent -0.87,-0.35 0.87,0.6, height 1.2
0805 [mm] "0805 from SM-752 data"
  rect 1.3x1.5 smd: 1(-0.85,0) 2(0.85,0)
  silkscreen extent -1.72,-0.97 1.72,0.97, body extent -1.1,-0.72 1.1,0.72, height 1.45
0805_HV [mil] "0805 with 30mil clearance between pads"
  rect 50x63 smd: 1(-40,0) 2(40,0)
  silkscreen extent -74,-40 74,40, body extent -43,-29 43,29, height 57
1206 [mm] "1206 from SM-752 data"
  rect 1.3x1.85 smd: 1(-1.45,0) 2(1.45,0)
  silkscreen extent -2.4,-1.21 2.4,1.21, body extent -1.7,-0.9 1.7,0.9, height 1.35
1206_180 [mm] "1206_180"
  rect 1.1x1.6 smd: 1(-1.7,0) 2(1.7,0)
  silkscreen extent -0.9,-1 0.9,1, body extent -1.75,-0.95 1.75,0.95, height 1.8
1206_190 [mm] "1206_190"
  rect 1.1x1.6 smd: 1(-1.7,0) 2(1.7,0)
  silkscreen extent -0.9,-1 0.9,1, body extent -1.75,-0.95 1.75,0.95, height 1.9
1210_270 [mm] "1210"
  rect 1.3x2.7 smd: 1(-1.45,0) 2(1.45,0)
  silkscreen extent -2.32,-1.57 2.32,1.57, body extent -1.7,-1.35 1.7,1.35, height 2.7
1210_280 [mm] "SMD, 2-Leads, Body 3.6x2.8mm, Height 2.8mm"
  rect 1.1x2.2 smd: 1(-1.65,0) 2(1.65,0)
  silkscreen extent -0.84,-1.4 0.84,1.4, body extent -1.8,-1.4 1.8,1.4, height 2.8
6032-28 [mm] "Medium Density IPC based on Vishay Sprague 293D datasheet."
  rect 2.55x2.3 smd: 1(-2.375,0) 2(2.375,0)
  silkscreen extent -3.96,-1.75 3.2,1.83, body extent -3.15,-1.75 3.15,1.75, height 2.8
Amphenol_901-144-8RFX [mm] "SMA Straight Jack, TH"
  round 2 hole 1.5: 1(0,0)
  round 2.2 hole 1.7: 2(-2.54,2.54) 3(-2.54,-2.54) 4(2.54,-2.54) 5(2.54,2.54)
  silkscreen extent -3.7,-3.7 3.7,3.7, body extent -3.7,-3.7 3.7,3.7, height 9.93
AssemblyNote [mil] "Assembly Note"
D0008A_N [mm] "SOIC, 8-Leads, Body 4.9x3.9mm, Pitch 1.27mm, IPC Medium Density"
  oval 1.45x0.6 smd: 1(-2.725,1.905) 2(-2.725,0.635) 3(-2.725,-0.635) 4(-2.725,-1.905) 5(2.725,-1.905) 6(2.725,-0.635) 7(2.725,0.635) 8(2.725,1.905)
  silkscreen extent -3.3,-2.5 0.9,2.5, body extent -3,-2.45 3,2.45, height 1.63
DBV0005A_N [mm] "SOT23, 5-Leads, Body 2.9x1.6mm, Pitch 0.95mm, Lead Span 2.8mm, IPC Medium Density"
  rrect17% 1x0.6 smd: 1(-1.375,0.95) 2(-1.375,0) 3(-1.375,-0.95) 4(1.375,-0.95) 5(1.375,0.95)
  silkscreen extent -1.63,-1.55 0.38,1.55, body extent -1.42,-1.46 1.42,1.46, height 1.09
DBV0006A_N [mm] "SOT23, 6-Leads, Body 2.9x1.6mm, Pitch 0.95mm, Lead Span 2.8mm, IPC Medium Density"
  rrect17% 1x0.6 smd: 1(-1.375,0.95) 2(-1.375,0) 3(-1.375,-0.95) 4(1.375,-0.95) 5(1.375,0) 6(1.375,0.95)
  silkscreen extent -1.68,-1.55 0.5,1.55, body extent -1.42,-1.46 1.42,1.46, height 1.12
DCK0005A_N [mm] "SOT353, 5-Leads, Body 2x1.3mm, Pitch 0.65mm, Lead Span 2.1mm, IPC Medium Density"
  rrect25% 0.85x0.4 smd: 1(-1.125,0.65) 2(-1.125,0) 3(-1.125,-0.65) 4(1.125,-0.65) 5(1.125,0.65)
  silkscreen extent -1.48,-1.02 0.55,1.1, body extent -1.14,-1 1.14,1, height 0.95
DGK0008A_N [mm] "TSOP, 8-Leads, Body 3x3mm, Pitch 0.65mm, IPC Medium Density"
  oval 1.35x0.45 smd: 1(-2.225,0.975) 2(-2.225,0.325) 3(-2.225,-0.325) 4(-2.225,-0.975) 5(2.225,-0.975) 6(2.225,-0.325) 7(2.225,0.325) 8(2.225,0.975)
  silkscreen extent -2.75,-1.55 0.95,1.55, body extent -2.45,-1.5 2.45,1.5, height 0.96
DGN0008D_N [mm] "TSOP, 8-Leads, Body 3x3mm, Pitch 0.65mm, Thermal Pad 1.89x1.57mm, IPC Medium Density"
  rrect100% 1.35x0.45 smd: 1(-2.225,0.975) 2(-2.225,0.325) 3(-2.225,-0.325) 4(-2.225,-0.975) 5(2.225,-0.975) 6(2.225,-0.325) 7(2.225,0.325) 8(2.225,0.975)
  rrect6% 1.57x1.89 smd: 9(0,0)
  silkscreen extent -2.73,-1.55 0.95,1.55, body extent -2.46,-1.5 2.46,1.5, height 1.1
DR73 [mm]
  rect 2.5x3.25 smd: 1(-3,0) 2(3,0)
  silkscreen extent -4.75,-3.8 4.75,3.8, body extent -3.8,-3.8 3.8,3.8, height 3.55
Fiducial10-20 [mm]
  round 1 smd mask+0.5: 1(0,0)
Keystone_1902C [mil] "Hex Standoff, 4-40 threaded, nylon"
  body extent -145,-126 146,126, height 501
MTC16_N [mm] "TSOP, 16-Leads, Body 5x4.4mm, Pitch 0.65mm, IPC Medium Density"
  oval 1.7x0.35 smd: 1(-2.85,2.275) 2(-2.85,1.625) 3(-2.85,0.975) 4(-2.85,0.325) 5(-2.85,-0.325) 6(-2.85,-0.975) 7(-2.85,-1.625) 8(-2.85,-2.275) 9(2.85,-2.275) 10(2.85,-1.625) 11(2.85,-0.975) 12(2.85,-0.325) 13(2.85,0.325) 14(2.85,0.975) 15(2.85,1.625) 16(2.85,2.275)
  silkscreen extent -2.97,-2.55 1.6,3.12, body extent -2.25,-2.55 2.25,2.55, height 1.1
MUA08A_N [mm] "TSOP, 8-Leads, Body 3x3mm, Pitch 0.65mm, IPC Medium Density"
  oval 1.7x0.45 smd: 1(-2.1,0.975) 2(-2.1,0.325) 3(-2.1,-0.325) 4(-2.1,-0.975) 5(2.1,-0.975) 6(2.1,-0.325) 7(2.1,0.325) 8(2.1,0.975)
  silkscreen extent -2.22,-1.55 0.85,1.88, body extent -1.6,-1.6 1.6,1.6, height 1.09
Net-Tie_50milWide_30milLong [mil] "50mil net tie, no solder mask opening, no solder paste"
  rect 30x100 on Mid1 paste-20 mask-20: 1(-15,0) 2(15,0)
NR3015 [mm] "SMD, 2-Leads, Body 3x3mm"
  rrect12% 0.8x2.7 smd: 1(-1.1,0) 2(1.1,0)
  silkscreen extent -0.3,-1.6 0.3,1.6, body extent -1.5,-1.5 1.5,1.5, height 1.5
"NY PMS 440 0025 PH" [mm] "4-40 nylon screw and mounting hole"
  round 8 hole 3.2: 1(0,0)
  body extent -3.3,-3.3 3.3,3.3, height 2.69
Pb-Free_Overlay_Small [mil]
  silkscreen extent -46,-46 46,46
PogoPad [mil] "No Solder Paste"
  round 70 smd paste-35: 1(0,0)
PowerDI123 [mm] "Diodes Inc recommended land pattern, document number DS30628 Rev. 6-2"
  rect 2.2x1.4 smd: 1(-1.275,0)
  rect 0.9x1.4 smd: 2(1.275,0)
  silkscreen extent -3.1,-1.09 1.76,1.09, body extent -2.38,-0.97 1.52,0.96, height 1
PW0016A_N [mm] "TSOP, 16-Leads, Body 5x4.4mm, Pitch 0.65mm, IPC Medium Density"
  oval 1.4x0.45 smd: 1(-2.95,2.275) 2(-2.95,1.625) 3(-2.95,0.975) 4(-2.95,0.325) 5(-2.95,-0.325) 6(-2.95,-0.975) 7(-2.95,-1.625) 8(-2.95,-2.275) 9(2.95,-2.275) 10(2.95,-1.625) 11(2.95,-0.975) 12(2.95,-0.325) 13(2.95,0.325) 14(2.95,0.975) 15(2.95,1.625) 16(2.95,2.275)
  silkscreen extent -3.5,-2.55 1.85,2.75, body extent -3.21,-2.5 3.21,2.5, height 1
PWP0016G_N [mm] "TSOP, 16-Leads, Body 5x4.4mm, Pitch 0.65mm, Thermal Pad 2.41x3.29 mm, IPC Medium Density"
  rrect22% 1.4x0.45 smd: 1(-2.95,2.275) 2(-2.95,1.625) 3(-2.95,0.975) 4(-2.95,0.325) 5(-2.95,-0.325) 6(-2.95,-0.975) 7(-2.95,-1.625) 8(-2.95,-2.275) 9(2.95,-2.275) 10(2.95,-1.625) 11(2.95,-0.975) 12(2.95,-0.325) 13(2.95,0.325) 14(2.95,0.975) 15(2.95,1.625) 16(2.95,2.275)
  rrect6% 3.4x5 smd paste-1.7 mask-1.7: 17(0,0)
  rrect4% 2.41x3.29 on Bottom Paste: 17(0,0)
  rrect4% 2.41x3.29 on Bottom Solder: 17(0,0)
  silkscreen extent -3.5,-2.55 1.5,2.73, body extent -3.21,-2.5 3.21,2.5, height 0.99
RGE0024H [mm] "QFN, 24-Leads, Body 4x4mm, Pitch 0.5mm, Thermal Pad 2.7x2.7mm, TI Recommended"
  rrect40% 0.6x0.25 smd: 1(-1.9,1.25) 2(-1.9,0.75) 3(-1.9,0.25) 4(-1.9,-0.25) 5(-1.9,-0.75) 6(-1.9,-1.25) 13(1.9,-1.25) 14(1.9,-0.75) 15(1.9,-0.25) 16(1.9,0.25) 17(1.9,0.75) 18(1.9,1.25)
  rrect40% 0.25x0.6 smd: 7(-1.25,-1.9) 8(-0.75,-1.9) 9(-0.25,-1.9) 10(0.25,-1.9) 11(0.75,-1.9) 12(1.25,-1.9) 19(1.25,1.9) 20(0.75,1.9) 21(0.25,1.9) 22(-0.25,1.9) 23(-0.75,1.9) 24(-1.25,1.9)
  rrect4% 2.7x2.7 smd paste-1.35: 25(0,0)
  silkscreen extent -2.22,-2.22 2.22,2.22, body extent -2.07,-2.07 2.07,2.07, height 1.01
RGT0016A [mm] "QFN, 16-Leads, Body 3x3mm, Pitch 0.5mm, Thermal Pad 1.45x1.45mm, TI Recommended"
  rrect42% 0.6x0.24 smd: 1(-1.4,0.75) 2(-1.4,0.25) 3(-1.4,-0.25) 4(-1.4,-0.75) 9(1.4,-0.75) 10(1.4,-0.25) 11(1.4,0.25) 12(1.4,0.75)
  rrect42% 0.24x0.6 smd: 5(-0.75,-1.4) 6(-0.25,-1.4) 7(0.25,-1.4) 8(0.75,-1.4) 13(0.75,1.4) 14(0.25,1.4) 15(-0.25,1.4) 16(-0.75,1.4)
  rrect7% 1.45x1.45 smd paste-0.725: 17(0,0)
  silkscreen extent -1.72,-1.73 1.72,1.73, body extent -1.57,-1.57 1.58,1.58, height 1.01
RGW0020A [mm] "QFN, 20-Leads, Body 5x5mm, Pitch 0.65mm, Thermal Pad 3.15x3.15mm, TI Recommended"
  oval 0.75x0.3 smd: 1(-2.325,1.3) 2(-2.325,0.65) 3(-2.325,0) 4(-2.325,-0.65) 5(-2.325,-1.3) 11(2.325,-1.3) 12(2.325,-0.65) 13(2.325,0) 14(2.325,0.65) 15(2.325,1.3)
  oval 0.3x0.75 smd: 6(-1.3,-2.325) 7(-0.65,-2.325) 8(0,-2.325) 9(0.65,-2.325) 10(1.3,-2.325) 16(1.3,2.325) 17(0.65,2.325) 18(0,2.325) 19(-0.65,2.325) 20(-1.3,2.325)
  rect 3.15x3.15 smd paste-1.575: 21(0,0)
  silkscreen extent -2.73,-2.73 2.73,2.73, body extent -2.58,-2.57 2.57,2.58, height 1.01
